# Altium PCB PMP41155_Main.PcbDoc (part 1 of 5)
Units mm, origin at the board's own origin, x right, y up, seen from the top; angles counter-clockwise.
Board outline 74 x 146.5 mm, 8 copper layers (Top Layer, Signal Layer 1, Signal Layer 2, Signal Layer 3, Signal Layer 4, Signal Layer 5, Signal Layer 6, Bottom Layer), stack 1.534 mm thick; 249 components, 190 nets, 902 pads, 747 vias.
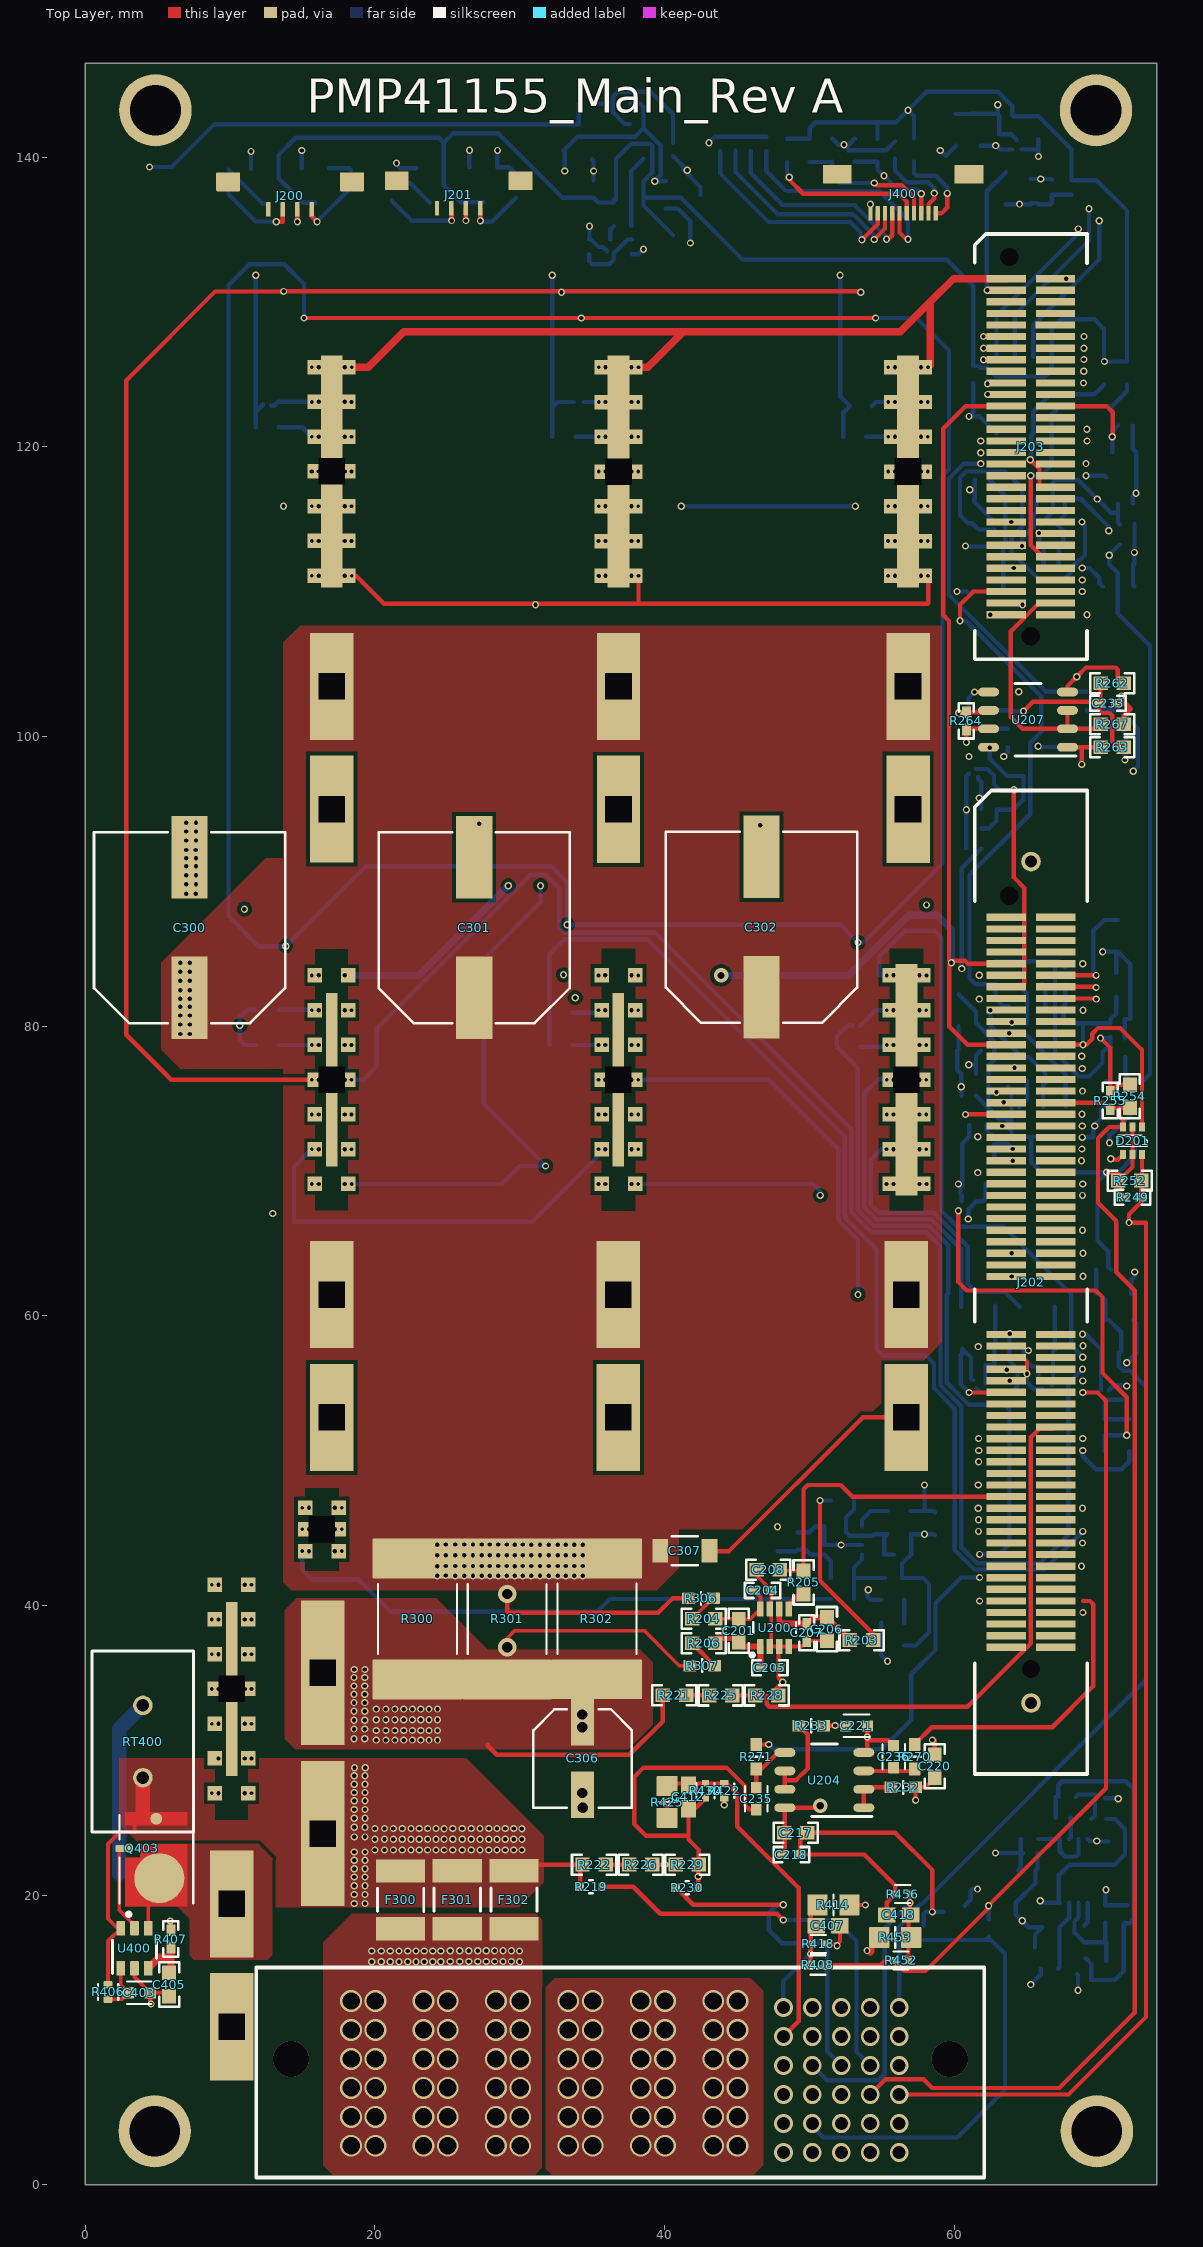
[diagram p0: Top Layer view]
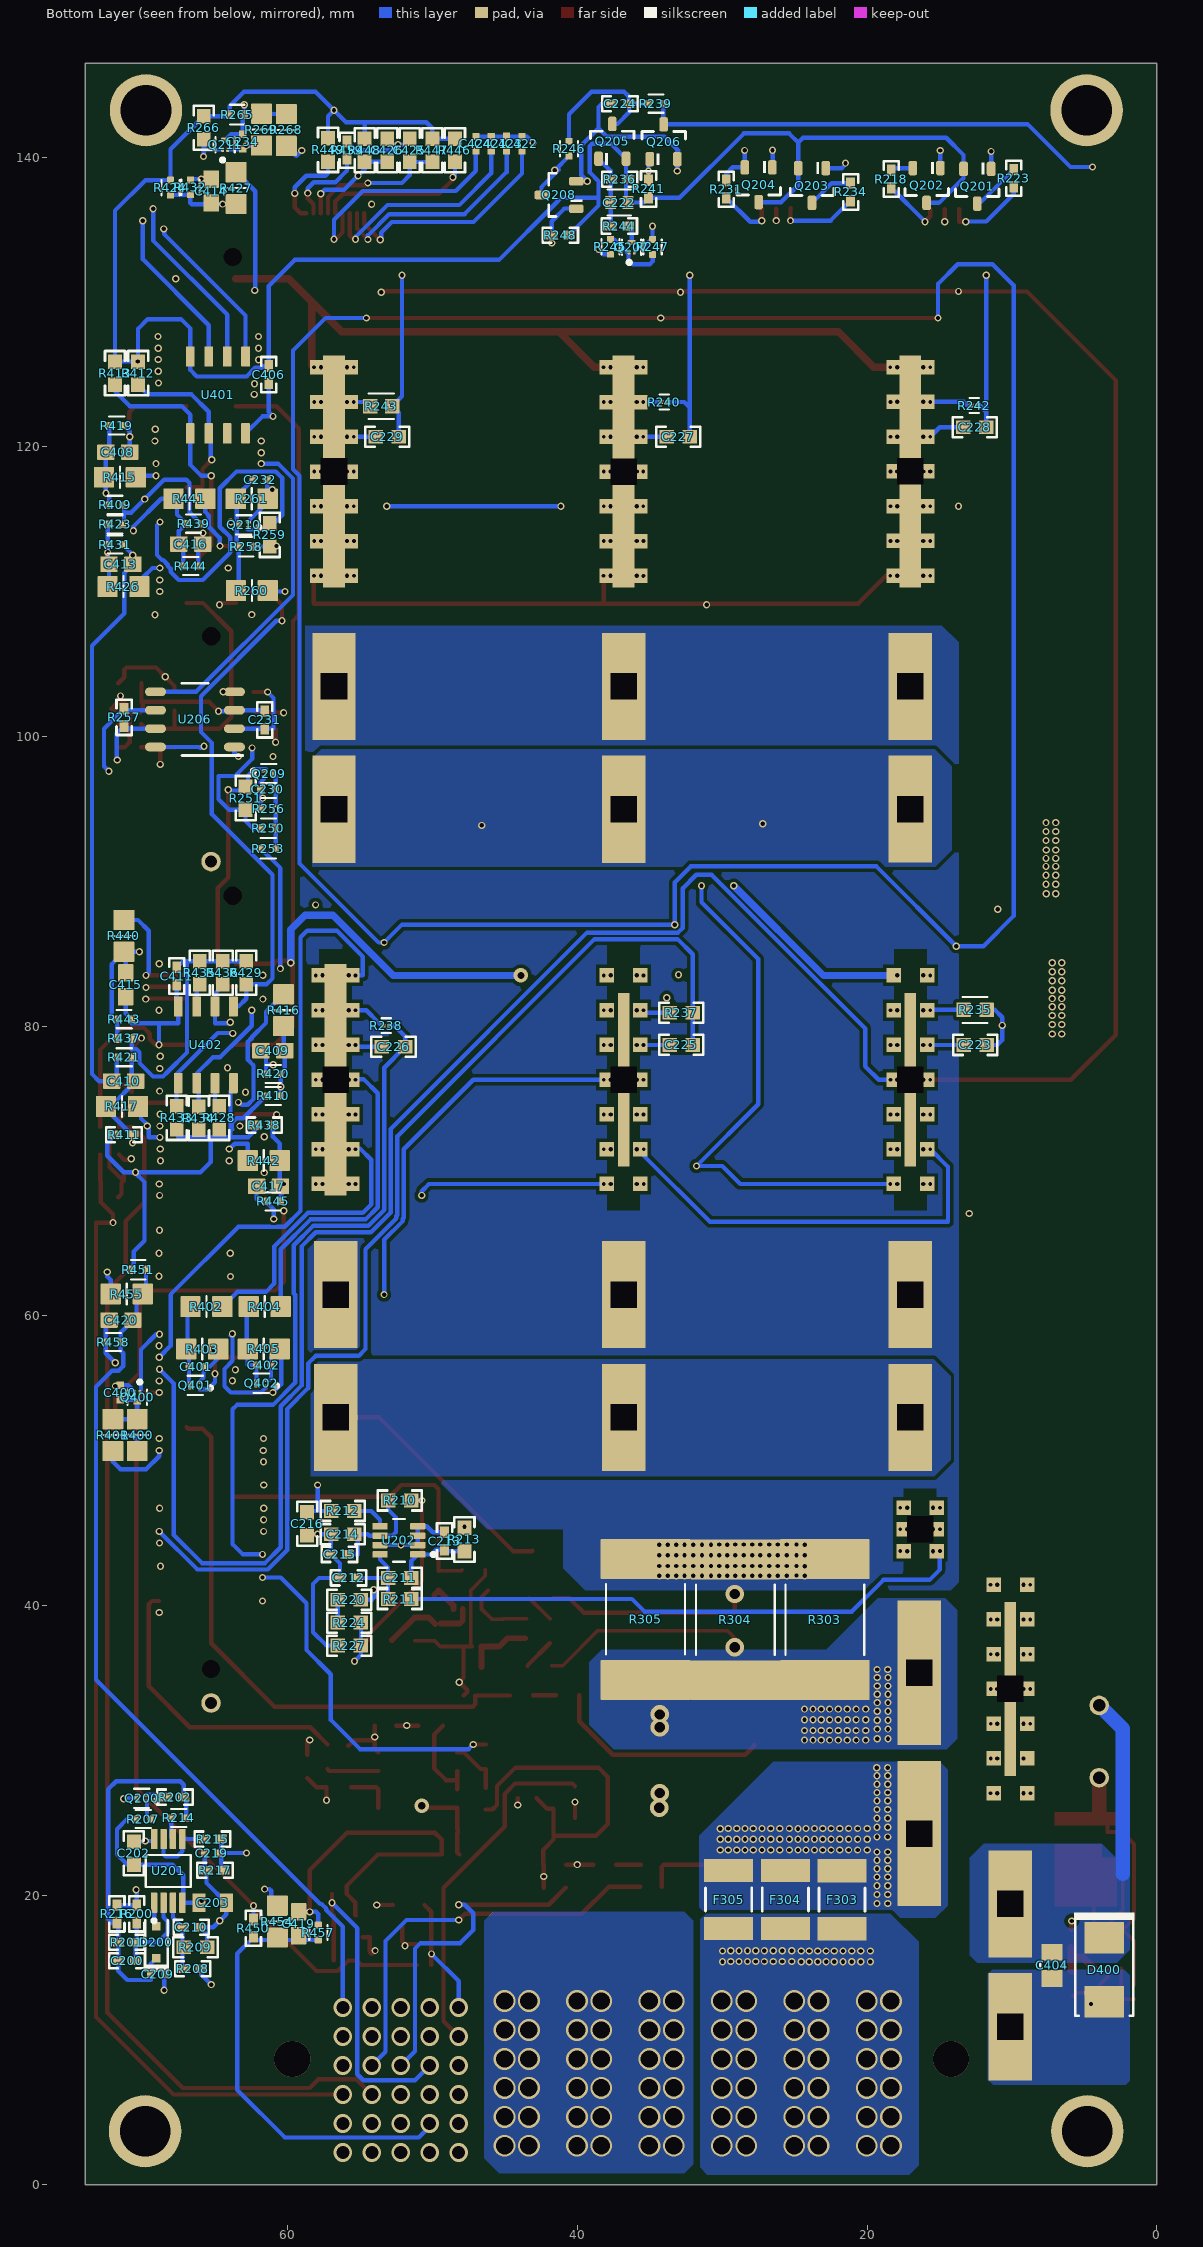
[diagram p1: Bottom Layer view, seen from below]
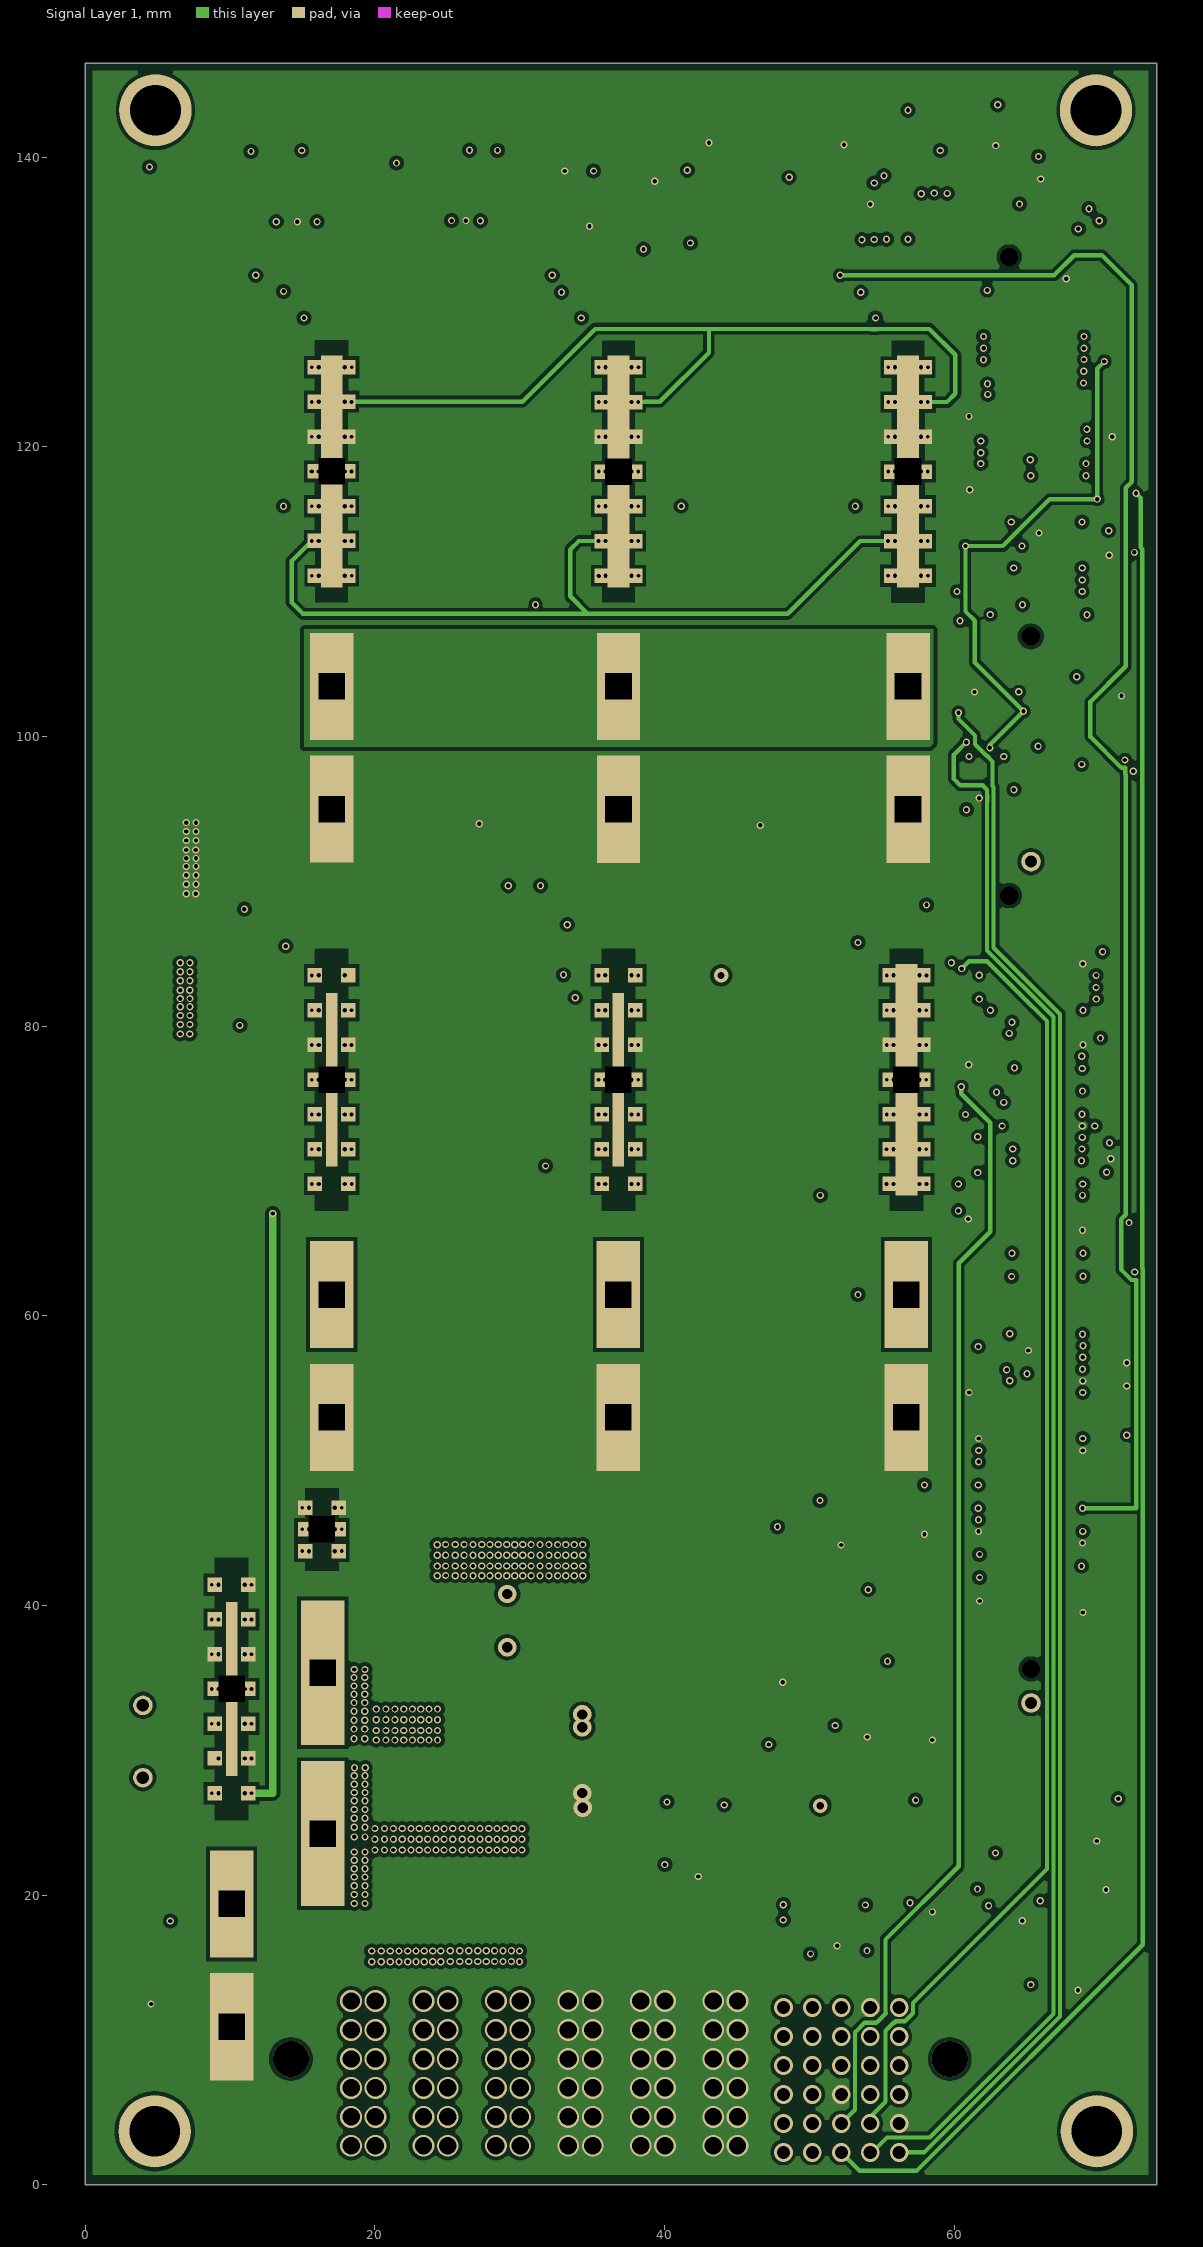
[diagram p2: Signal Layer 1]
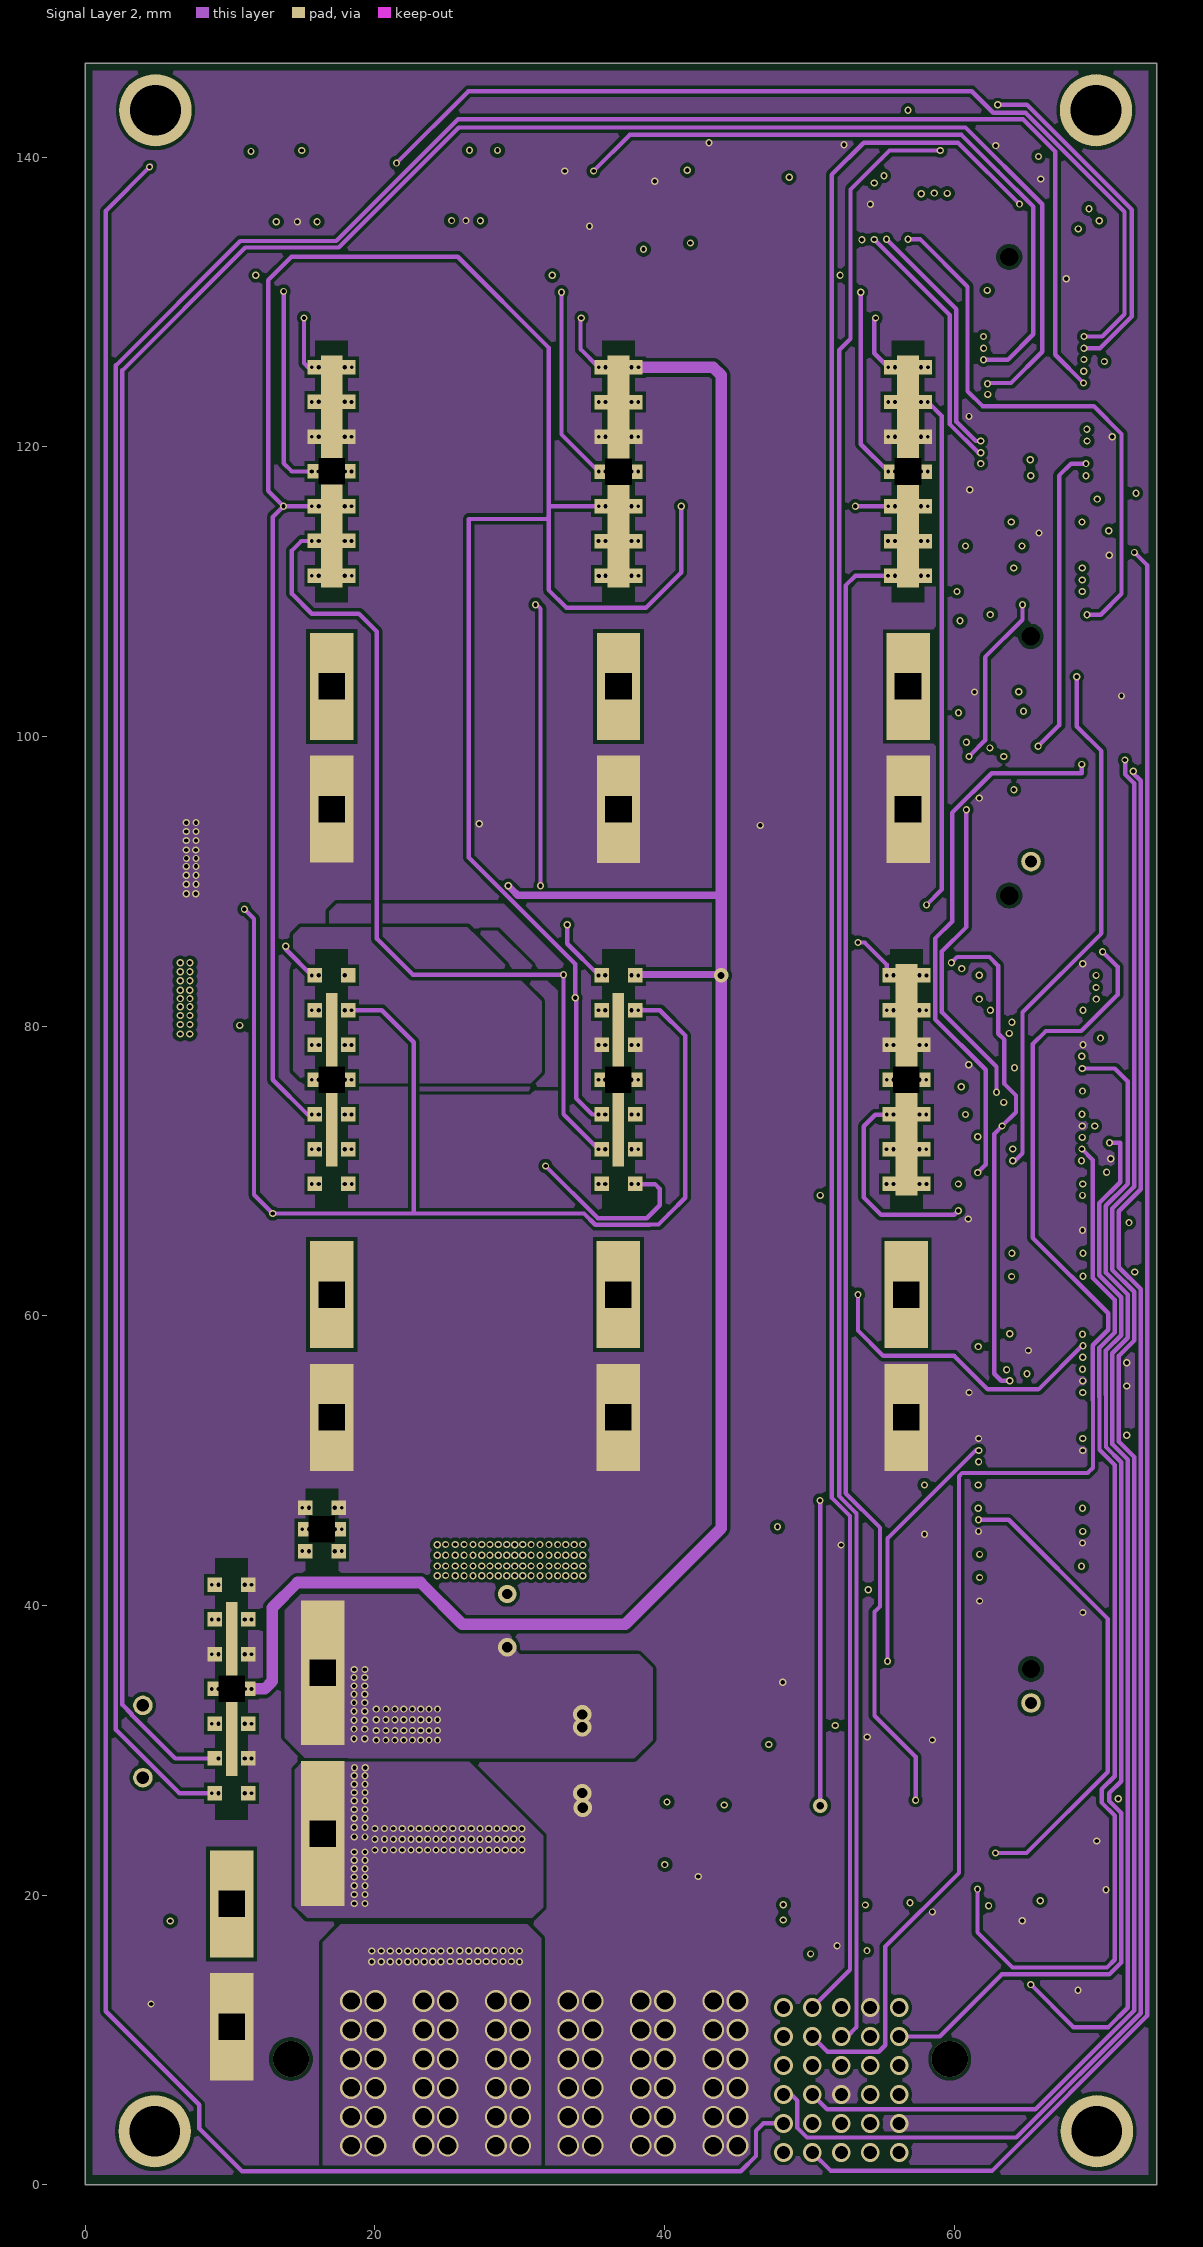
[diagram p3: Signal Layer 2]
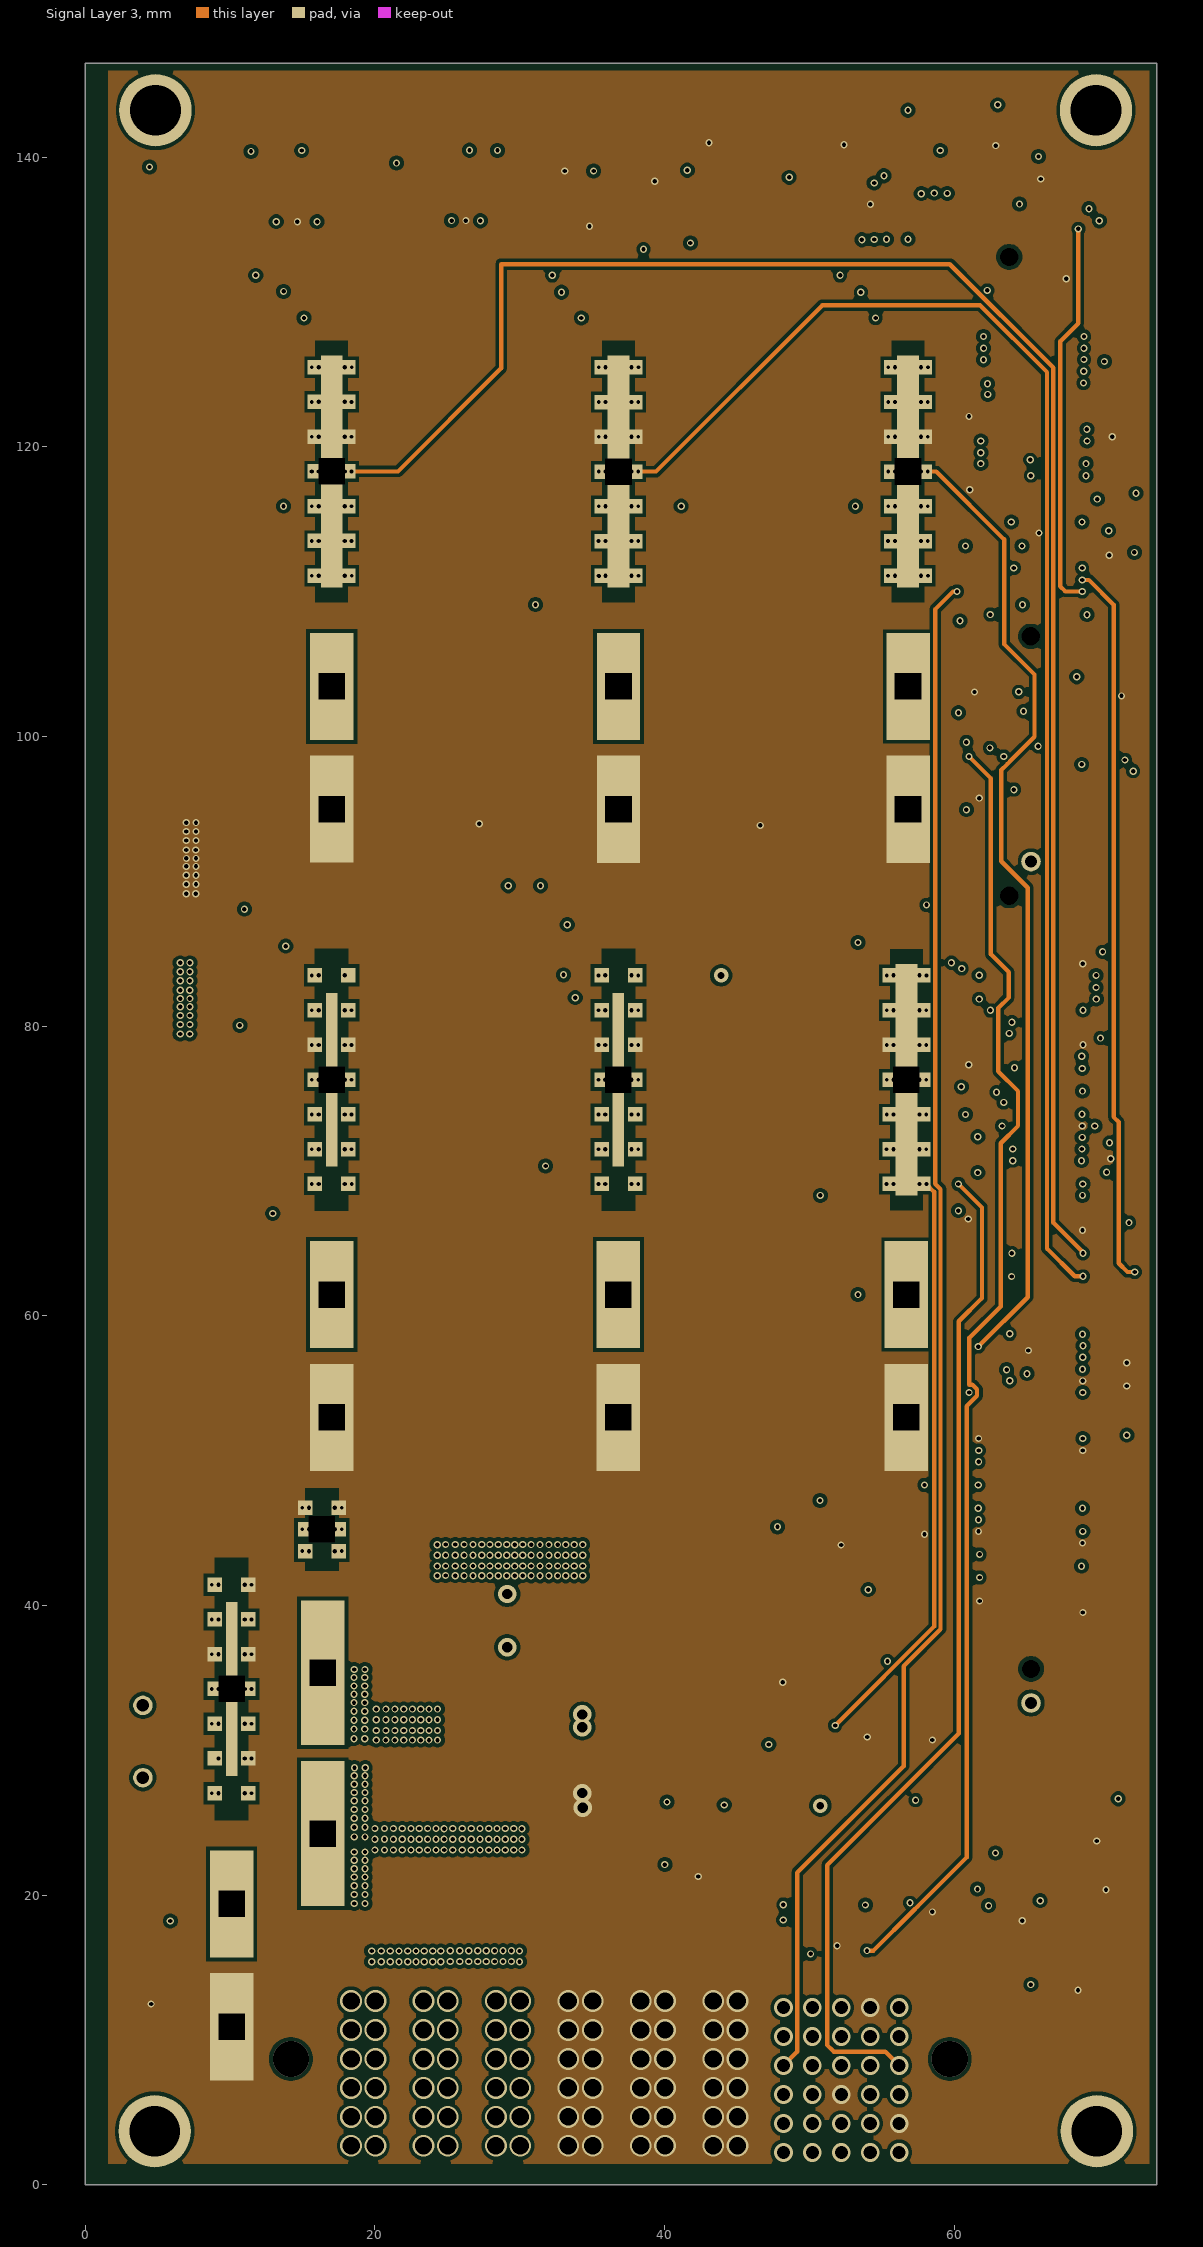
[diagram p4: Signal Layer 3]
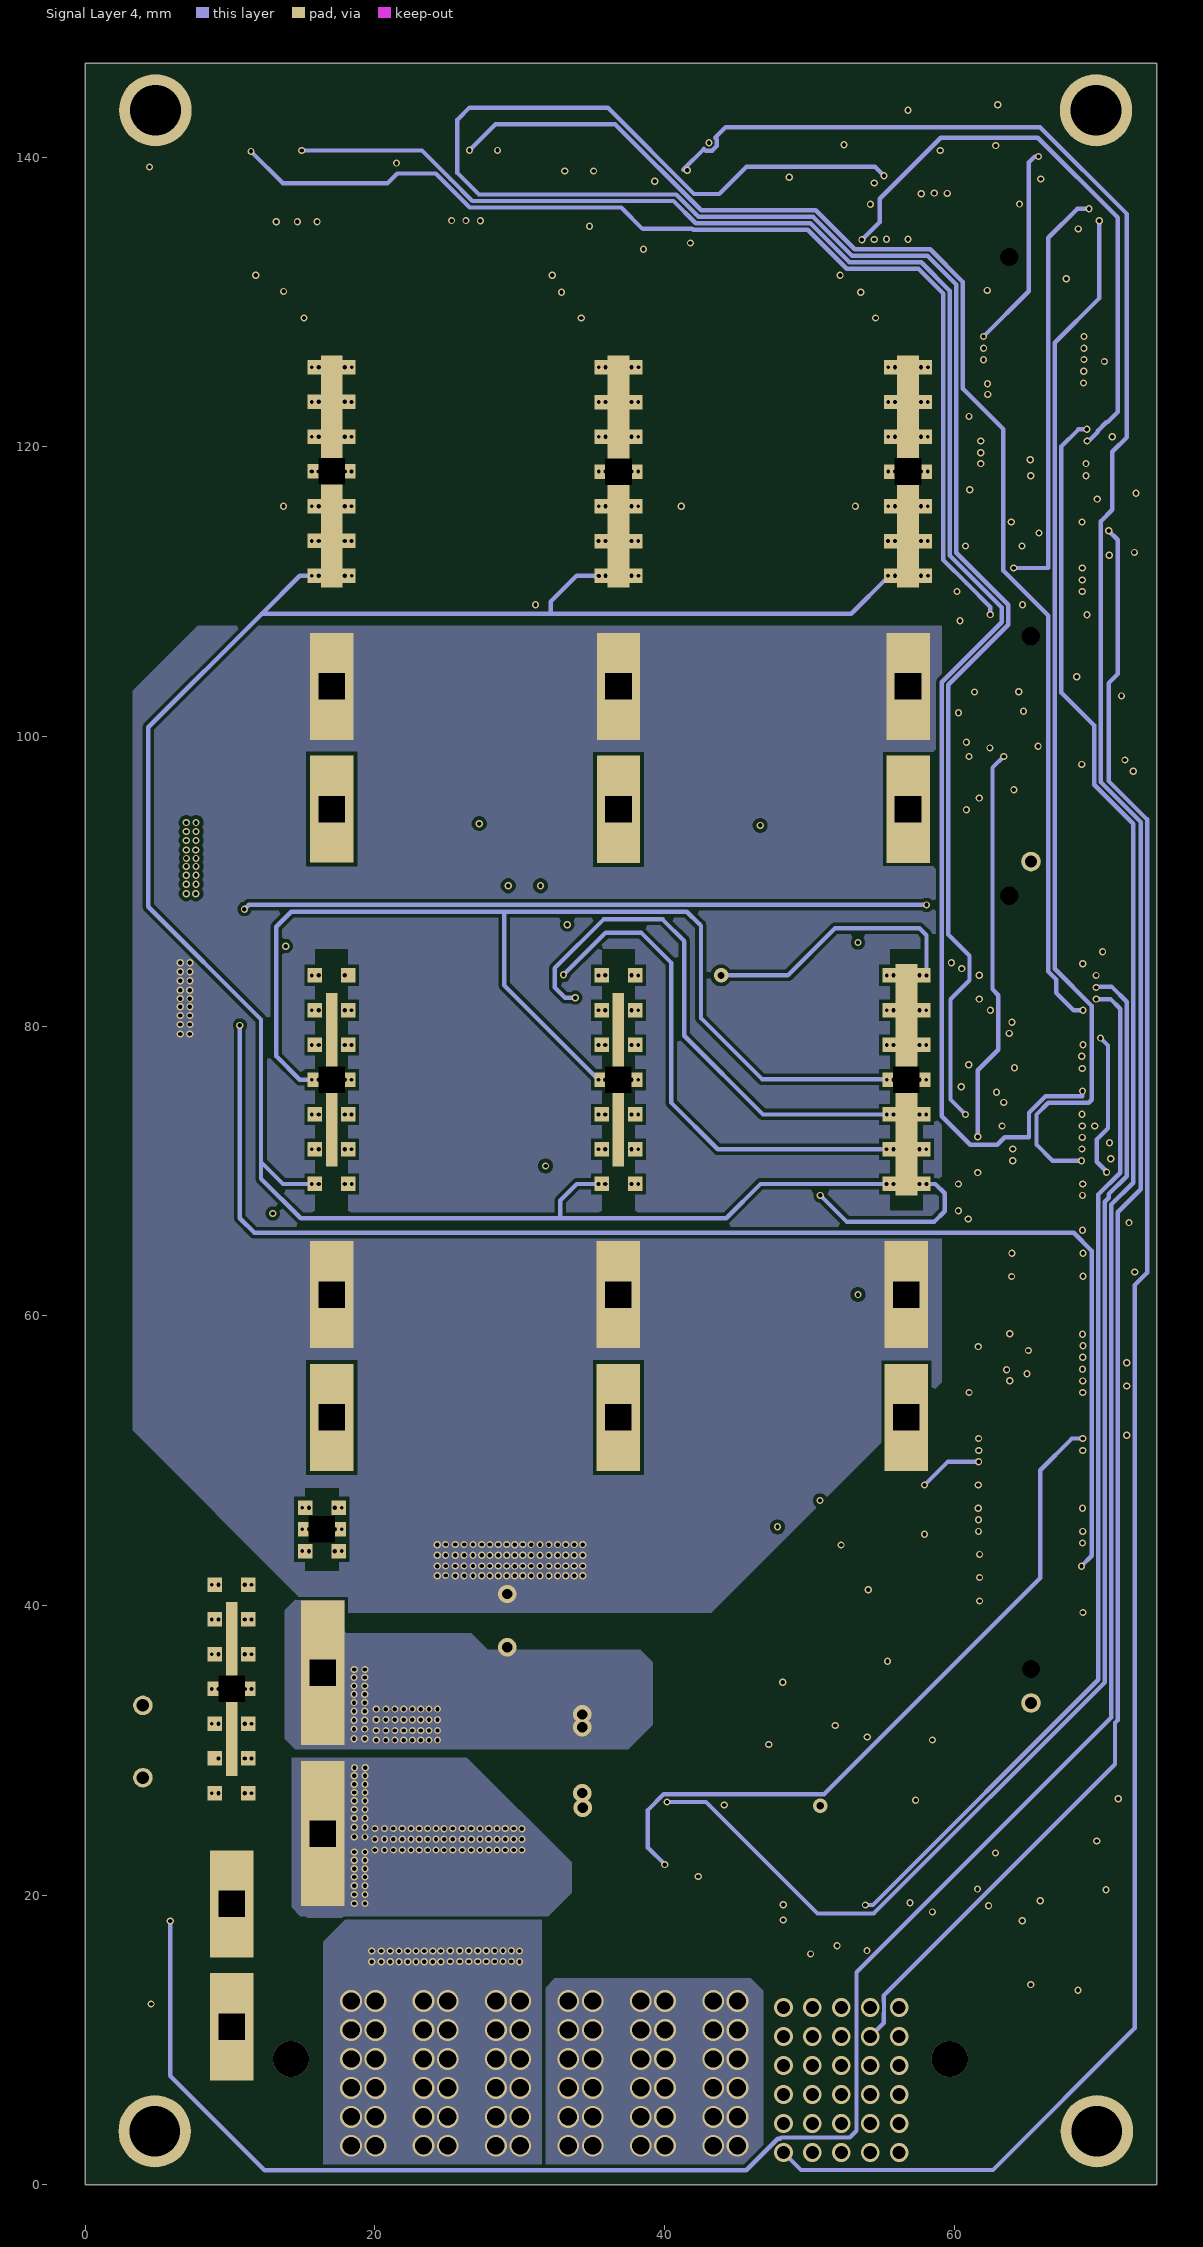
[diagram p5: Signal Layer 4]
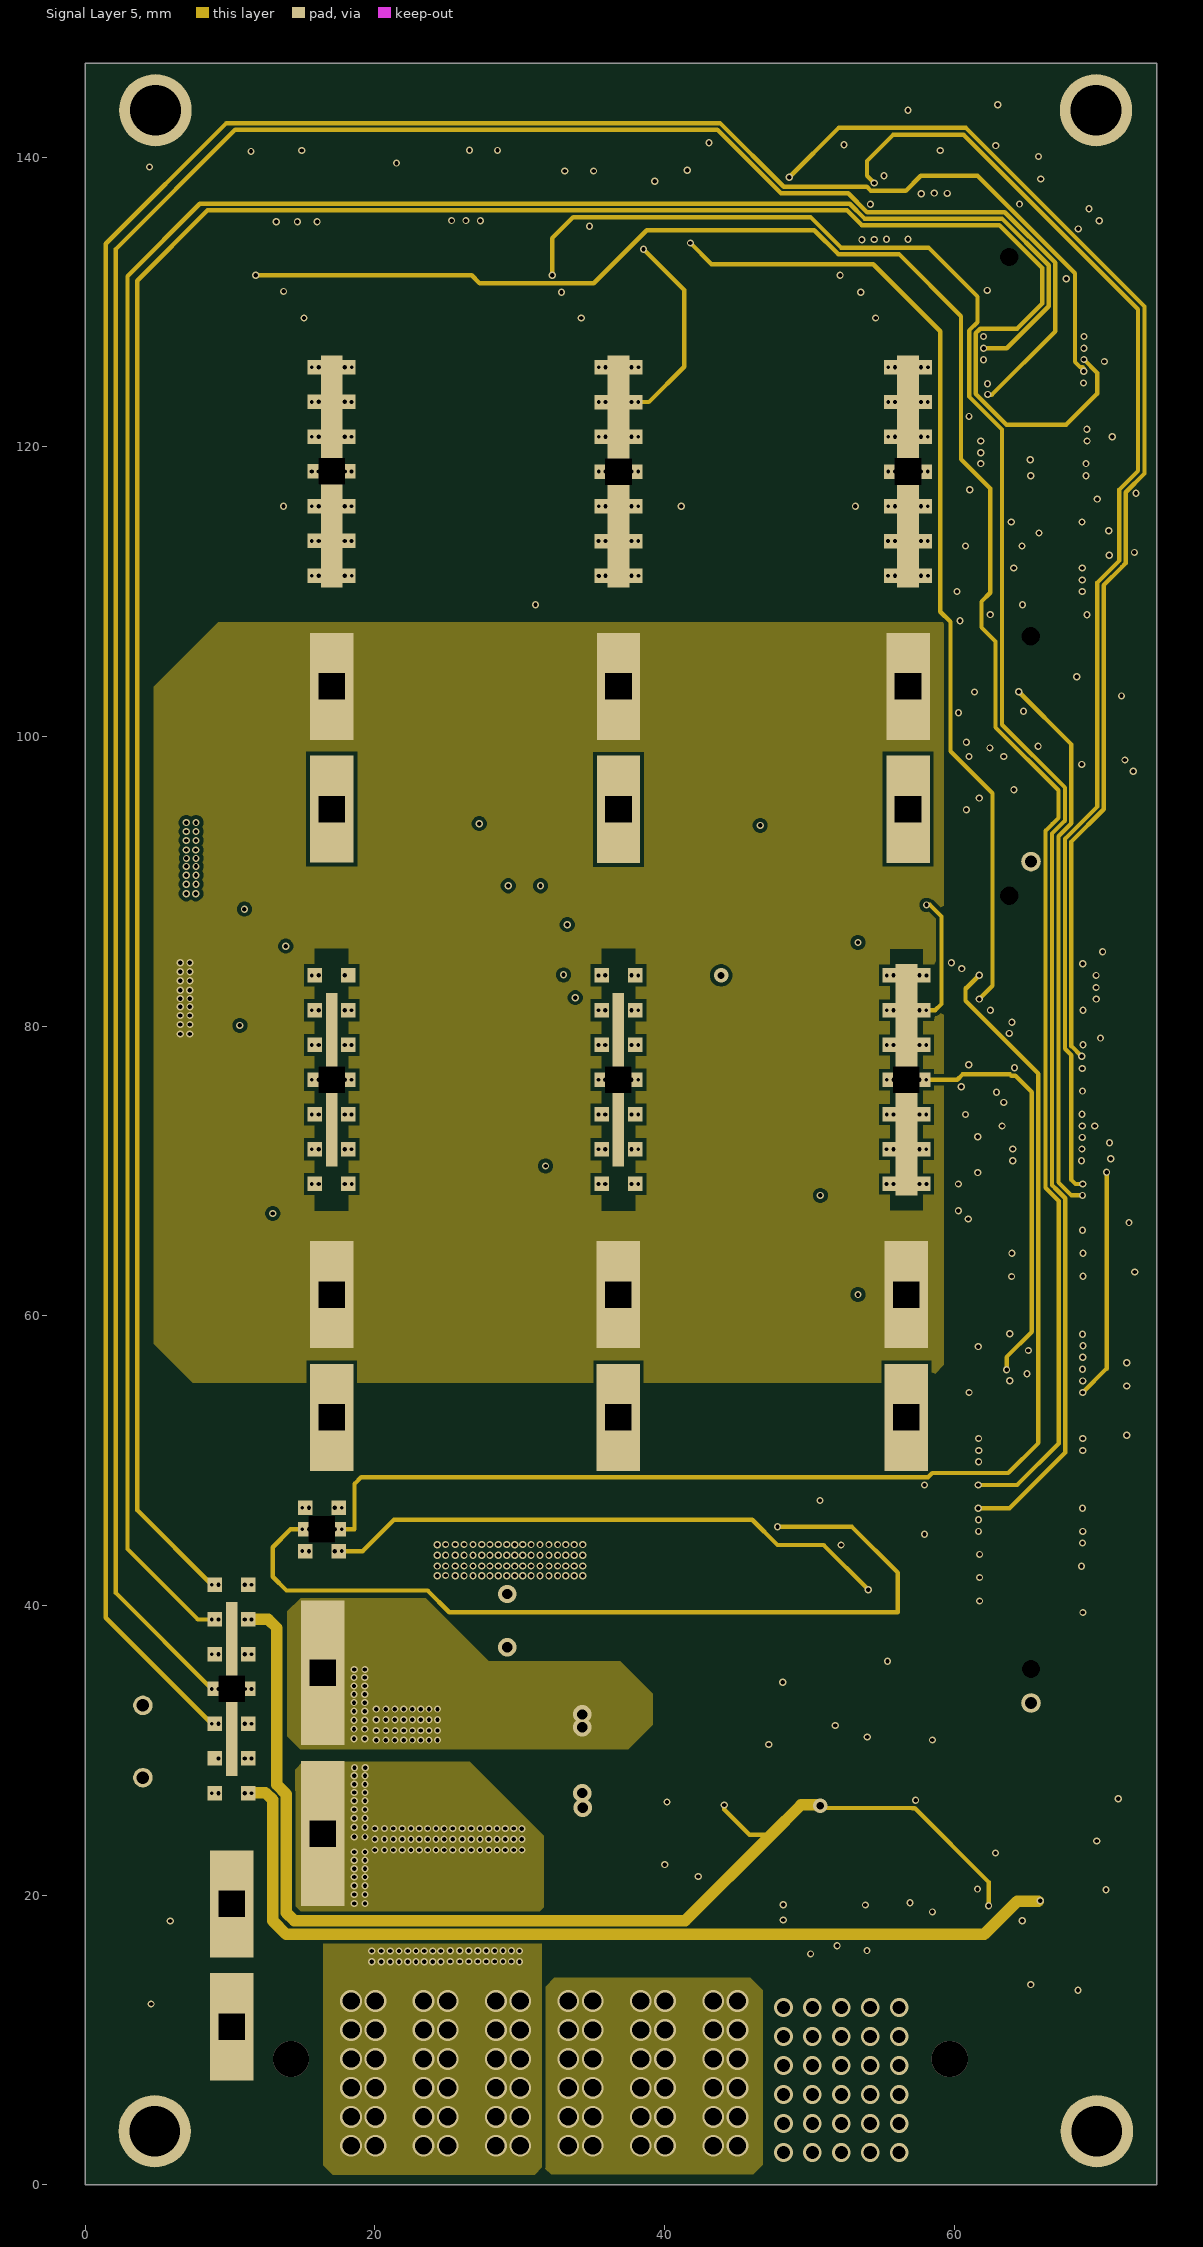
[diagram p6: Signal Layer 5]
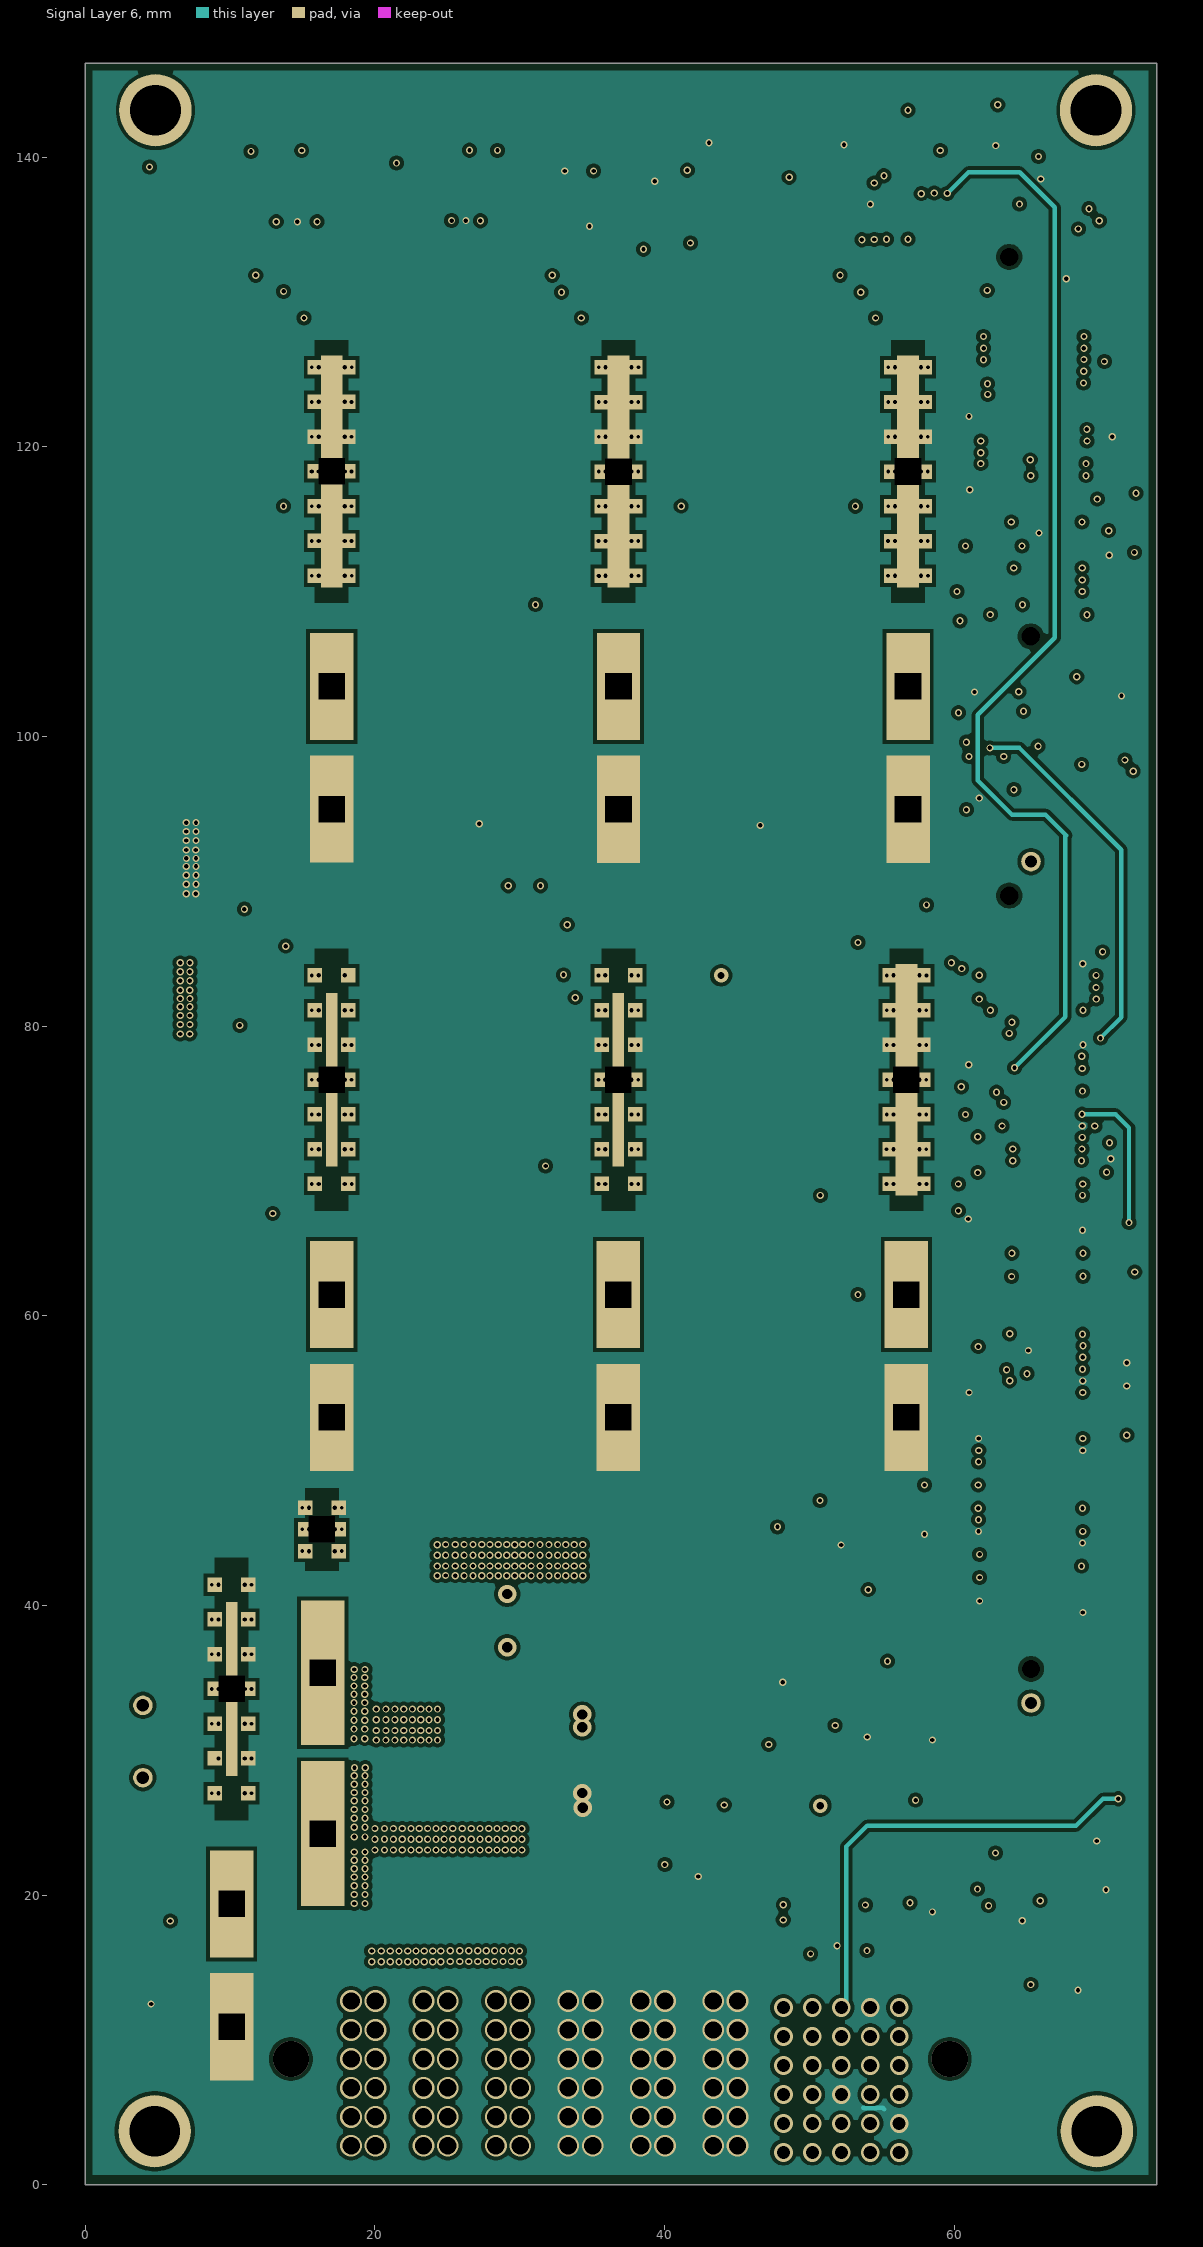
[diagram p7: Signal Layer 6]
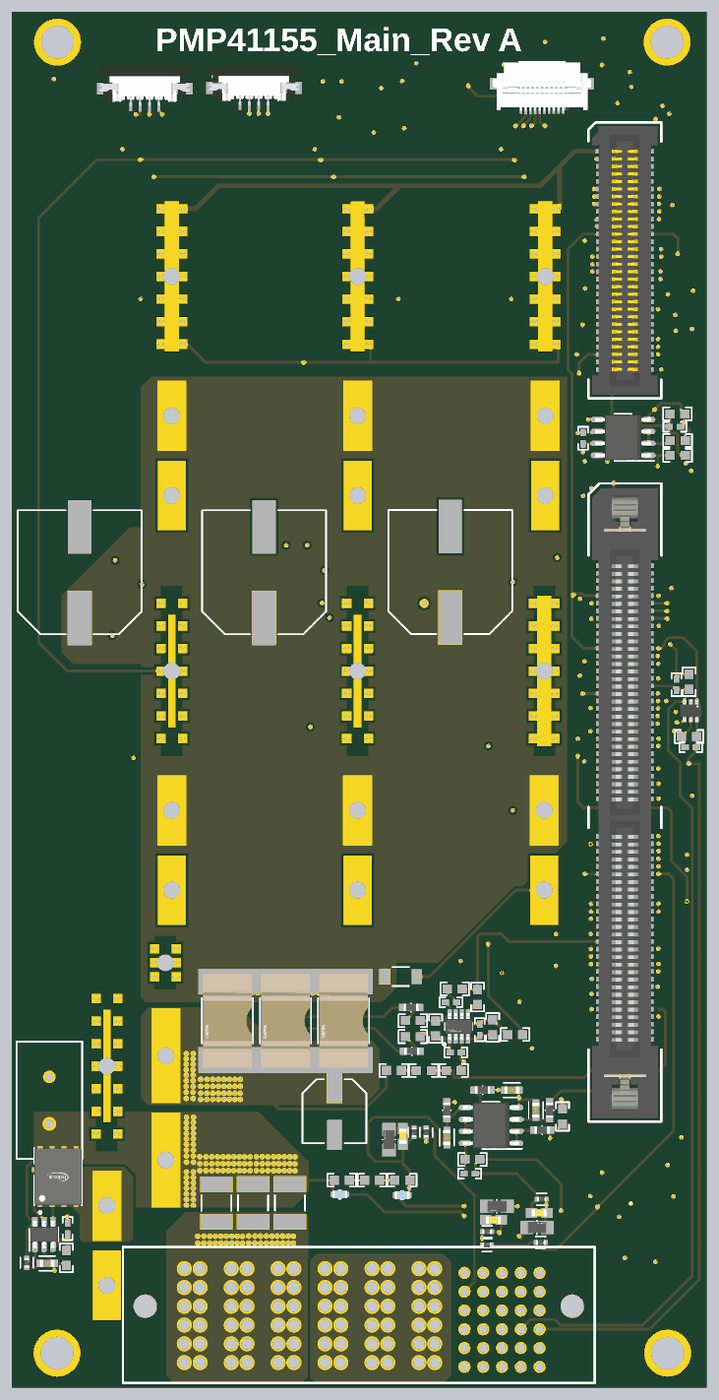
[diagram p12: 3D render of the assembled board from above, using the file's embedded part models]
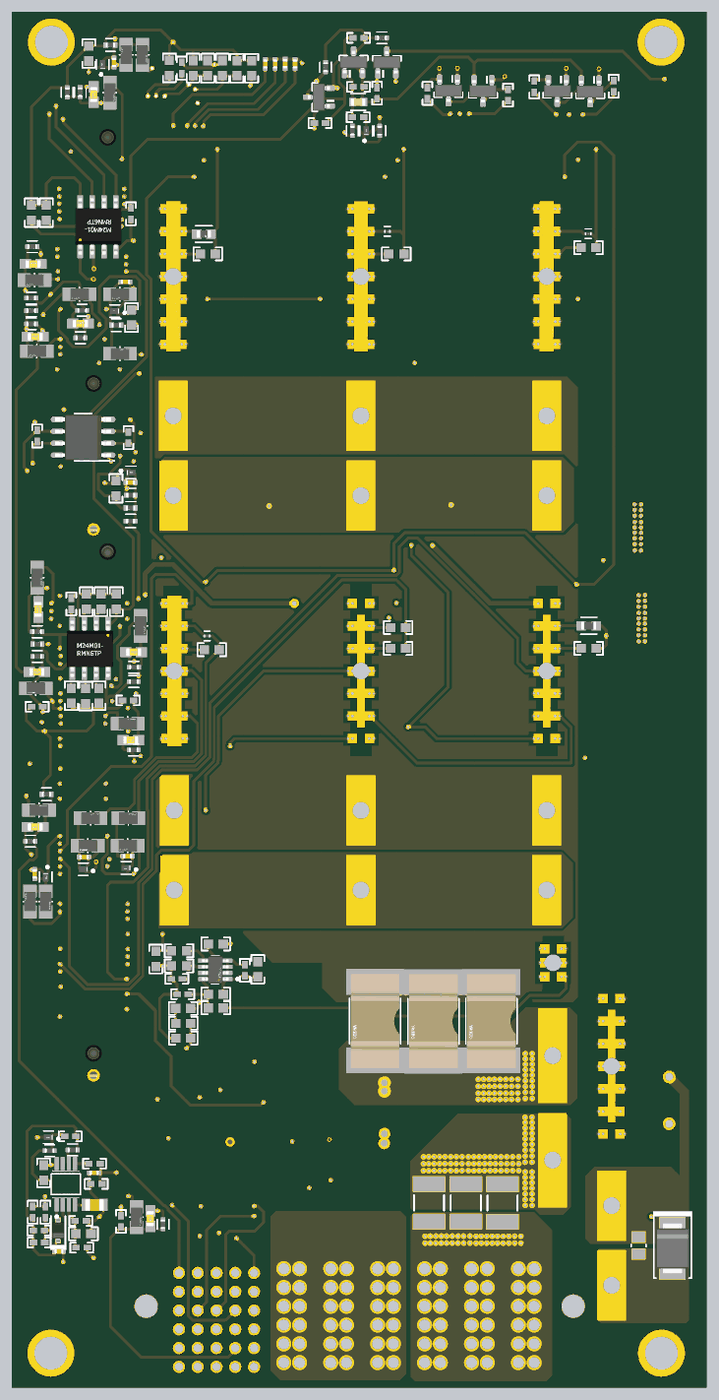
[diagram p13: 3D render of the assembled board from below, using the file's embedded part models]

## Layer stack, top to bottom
Top Solder: solder mask 0.01, Solder Resist, Dk 3.5
Top Layer: signal copper 0.0711
Dielectric1: prepreg 0.127, FR-4, Dk 4.2
Signal Layer 1: signal copper 0.0711
Dielectric 2: core 0.1524, FR-4, Dk 4.2
Signal Layer 2: signal copper 0.0711
Dielectric 3: prepreg 0.127, Dk 4.2
Signal Layer 3: signal copper 0.0711
Dielectric 4: core 0.1524, Dk 4.2
Signal Layer 4: signal copper 0.0711
Dielectric 6: prepreg 0.127, Dk 4.2
Signal Layer 5: signal copper 0.0711
Dielectric 7: core 0.1524, Dk 4.2
Signal Layer 6: signal copper 0.0711
Dielectric 5: prepreg 0.127, Dk 4.2
Bottom Layer: signal copper 0.0711
Bottom Solder: solder mask 0.01, Solder Resist, Dk 3.5

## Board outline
0,0 0,146.5 74,146.5 74,0

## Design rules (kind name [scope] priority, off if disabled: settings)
AcuteAngle [All] p1: minimum=4.50000000000000E+0001 checktracksonly=FALSE
AssemblyTestPointUsage [All] p1: valid=2
BoardOutlineClearance BoardOutlineClearance_MountingHoles [OnCopper and InComponentClass('Mounting Holes')] p1: gap=1.016 ignorepadtopadclearanceinfootprint=FALSE
BoardOutlineClearance BoardOutlineClearance_Poly [OnCopper and IsPoly] p2: gap=0.508 ignorepadtopadclearanceinfootprint=FALSE
BoardOutlineClearance [OnCopper and Not InComponentClass('Logo') and not InComponentClass('FiducialMark') and not InRegion(1000,500,4000,800) and not InPoly] p3: gap=0.254 ignorepadtopadclearanceinfootprint=FALSE
Clearance Clearance_1 [InNetClass('HV') vs Not InNetClass('HV')] p1: gap=0.508 ignorepadtopadclearanceinfootprint=FALSE
Clearance Clearance_Keepouts [((IsTrack Or IsArc) And Not InPoly) And IsFree and IsKeepOut vs ((IsTrack Or IsArc) And Not InPoly) And IsFree and IsKeepOut] p2: gap=0 ignorepadtopadclearanceinfootprint=FALSE
Clearance Clearance_Poly [InPolygon] p3: gap=0.254 ignorepadtopadclearanceinfootprint=FALSE
Clearance Clearance_FiducialMark [IsKeepOut and InComponentClass('FiducialMark') vs IsPad and InComponentClass('FiducialMark')] p4: gap=0 ignorepadtopadclearanceinfootprint=FALSE
Clearance [All] p5: gap=0.147 ignorepadtopadclearanceinfootprint=FALSE
ComponentClearance ComponentClearance_MountingHoles_FiducialMarks [InComponentClass('Mounting Holes') vs InComponentClass('FiducialMark')] p1: gap=1.27 collisioncheckmode=3 verticalgap=0.254 showdistances=FALSE
ComponentClearance ComponentClearance_Shunt [InComponentClass('Header') vs InComponentClass('Shunt')] p2: gap=0 collisioncheckmode=3 verticalgap=0 showdistances=FALSE
ComponentClearance ComponentClearance_Logo [InComponentClass('Logo')] p3: gap=1.27 collisioncheckmode=3 verticalgap=0.254 showdistances=FALSE
ComponentClearance ComponentClearance_ScrewToNut [(HasFootprint('NY PMS 440 0025 PH')) vs (HasFootprint('Keystone_1902C'))] p4: gap=0.127 collisioncheckmode=3 verticalgap=0.254 showdistances=FALSE
ComponentClearance ComponentClearance_MountingHoles [InComponentClass('Mounting Holes')] p5: gap=6.35 collisioncheckmode=3 verticalgap=2540 showdistances=FALSE
ComponentClearance ComponentClearance_SmallPassives [HasFootprint('0201*') or HasFootprint('0402*') or HasFootprint('0508') or HasFootprint('0603*') or HasFootprint('0612') or HasFootprint('0805*') or HasFootprint('0815*') or HasFootprint('0830*') or HasFootprint('1206*') or HasFootprint('1210*') or HasFootprint('1808*') or HasFootprint('1812*') or HasFootprint('1825*') or HasFootprint('2010*') or HasFootprint('2220*') or HasFootprint('2225*') or HasFootprint('2512*') or HasFootprint('2728*') or HasFootprint('3518*') vs HasFootprint('0201*') or HasFootprint('0402*') or HasFootprint('0508') or HasFootprint('0603*') or HasFootprint('0612') or HasFootprint('0805*') or HasFootprint('0815*') or HasFootprint('0830*') or HasFootprint('1206*') or HasFootprint('1210*') or HasFootprint('1808*') or HasFootprint('1812*') or HasFootprint('1825*') or HasFootprint('2010*') or HasFootprint('2220*') or HasFootprint('2225*') or HasFootprint('2512*') or HasFootprint('2728*') or HasFootprint('3518*')] p6: gap=0.254 collisioncheckmode=3 verticalgap=0.254 showdistances=FALSE
ComponentClearance ComponentClearance_THtoSMT [IsThruComponent vs IsSMTComponent] p7: gap=0.508 collisioncheckmode=3 verticalgap=0.762 showdistances=FALSE
ComponentClearance ComponentClearance_THtoTH [IsThruComponent vs IsThruComponent] p8: gap=0.508 collisioncheckmode=3 verticalgap=0.508 showdistances=FALSE
ComponentClearance [All] p9: gap=0.14 collisioncheckmode=3 verticalgap=0.14 showdistances=FALSE
DiffPairsRouting [All] p1: maxlimit=2.54 minlimit=0.254 mostfreqgap=0.254 toplayer_minwidth=0.381 toplayer_maxwidth=0.381 toplayer_prefwidth=0.381 midlayer1_minwidth=0.381 midlayer1_maxwidth=0.381 midlayer1_prefwidth=0.381 midlayer2_minwidth=0.381 midlayer2_maxwidth=0.381 midlayer2_prefwidth=0.381 midlayer3_minwidth=0.381 midlayer3_maxwidth=0.381 midlayer3_prefwidth=0.381 midlayer4_minwidth=0.381 midlayer4_maxwidth=0.381 midlayer4_prefwidth=0.381 midlayer5_minwidth=0.381 midlayer5_maxwidth=0.381 midlayer5_prefwidth=0.381 midlayer6_minwidth=0.381 midlayer6_maxwidth=0.381 midlayer6_prefwidth=0.381 bottomlayer_minwidth=0.381 bottomlayer_maxwidth=0.381 bottomlayer_prefwidth=0.381 maxuncoupledlength=25.4
FabricationTestPointUsage TestPointUsage [All] p1: valid=2 allowmultiple=FALSE
FabricationTestpoint Testpoint [All] p1: side=3 testpointundercomponent=TRUE minsize=1.016 maxsize=2.54 preferedsize=1.524 minholesize=0 maxholesize=1.016 preferedholesize=0.813 testpointgrid=0.025 allowsidetop=TRUE allowsidebottom=TRUE usegrid=TRUE gridtolerance=0
FanoutControl Fanout_LCC [IsLCC] p1: bgadir=Out bgaviamode=Centered fanoutstyle=Auto fanoutdirection=Alternating viagrid=0.025 // Fanout_LCC (Default Rule)
FanoutControl Fanout_BGA [IsBGA] p2: bgadir=Out bgaviamode=Centered fanoutstyle=Auto fanoutdirection=Alternating viagrid=0.025 // Fanout_BGA (Default Rule)
FanoutControl Fanout_Default [All] p4: bgadir=Out bgaviamode=Centered fanoutstyle=Auto fanoutdirection=Alternating viagrid=0.025 // Fanout_Default (Default Rule)
FanoutControl Fanout_Small [(CompPinCount < 5)] p5: bgadir=Out bgaviamode=Centered fanoutstyle=Auto fanoutdirection=OutThenIn viagrid=0.025 // Fanout_Small (Default Rule)
HoleSize [All] p1: absolutevalues=TRUE maxlimit=6.604 minlimit=0.2 maxpercent=80.000 minpercent=20.000
MinimumAnnularRing MinimumAnnularRing_ThermalPadVias [IsVia and InAnyComponent] p1: minimumring=0.15
MinimumAnnularRing [All] p2: minimumring=0.127
MinimumSolderMaskSliver MinimumSolderMaskSliver_Logo [InComponentClass('Logo') vs InComponentClass('Logo')] p1: minsoldermaskwidth=0.018
MinimumSolderMaskSliver [All] p2: minsoldermaskwidth=0.076
PlaneClearance [All] p1: clearance=0
PlaneConnect [All] p1: planeconnectstyle=Direct reliefexpansion=0.254 reliefentries=4 reliefconductorwidth=0.254 reliefairgap=0
PolygonConnect PolygonConnect_32 [All vs IsNamedPolygon('5V') Or  IsNamedPolygon('CS-_total_charge_current_battery') Or  IsNamedPolygon('5V') Or  IsNamedPolygon('CS-_total_charge_current_battery') Or  IsNamedPolygon('48Vout2') Or  IsNamedPolygon('48VOUT1') Or  IsNamedPolygon('SGND') Or  IsNamedPolygon('48Vout2') Or  IsNamedPolygon('CS-_total_discharge_current_bus') Or  IsNamedPolygon('5V') Or  IsNamedPolygon('48Vout2') Or  IsNamedPolygon('5V') Or  IsNamedPolygon('5V') Or  IsNamedPolygon('VBAT-') Or  IsNamedPolygon('5V') Or  IsNamedPolygon('48Vout2') Or  IsNamedPolygon('VBAT-') Or  IsNamedPolygon('48Vout2') Or  IsNamedPolygon('5V') Or  IsNamedPolygon('5V') Or  IsNamedPolygon('48Vout2') Or  IsNamedPolygon('5V') Or  IsNamedPolygon('CS-_total_charge_current_battery') Or  IsNamedPolygon('SGND') Or  IsNamedPolygon('SGND') Or  IsNamedPolygon('SGND') Or  IsNamedPolygon('CS-_total_discharge_current_bus') Or  IsNamedPolygon('SGND') Or  IsNamedPolygon('SGND') Or  IsNamedPolygon('CS-_total_charge_current_battery') Or  IsNamedPolygon('SGND') Or  IsNamedPolygon('48Vout1') Or  IsNamedPolygon('SGND') Or  IsNamedPolygon('CS-_total_charge_current_battery') Or  IsNamedPolygon('SGND') Or  IsNamedPolygon('VBAT-') Or  IsNamedPolygon('CS-_total_discharge_current_bus') Or  IsNamedPolygon('VBAT-') Or  IsNamedPolygon('VBAT-') Or  IsNamedPolygon('VBAT-') Or  IsNamedPolygon('CS-_total_discharge_current_bus') Or  IsNamedPolygon('SGND') Or  IsNamedPolygon('48Vout2') Or  IsNamedPolygon('VBAT-') Or  IsNamedPolygon('48Vout2') Or  IsNamedPolygon('VBAT-') Or  IsNamedPolygon('CS-') Or  IsNamedPolygon('SGND') Or  IsNamedPolygon('VBAT-') Or  IsNamedPolygon('SGND') Or  IsNamedPolygon('VBAT-') Or  IsNamedPolygon('48Vout1') Or  IsNamedPolygon('VBAT-') Or  IsNamedPolygon('CS-') Or  IsNamedPolygon('SGND') Or  IsNamedPolygon('48Vout1') Or  IsNamedPolygon('SGND') Or  IsNamedPolygon('VBAT-') Or  IsNamedPolygon('SGND') Or  IsNamedPolygon('CS-_total_charge_current_battery') Or  IsNamedPolygon('CS-_total_charge_current_battery') Or  IsNamedPolygon('VBAT-') Or  IsNamedPolygon('CS-_total_discharge_current_bus') Or  IsNamedPolygon('SGND') Or  IsNamedPolygon('CS-_total_charge_current_battery') Or  IsNamedPolygon('CS+_total_charge_current_battery') Or  IsNamedPolygon('48Vout1') Or  IsNamedPolygon('VBAT-') Or  IsNamedPolygon('SGND') Or  IsNamedPolygon('CS-_total_discharge_current_bus') Or  IsNamedPolygon('CS-_total_discharge_current_bus') Or  IsNamedPolygon('48Vout1') Or  IsNamedPolygon('SGND') Or  IsNamedPolygon('SGND') Or  IsNamedPolygon('CS-_total_charge_current_battery') Or  IsNamedPolygon('SGND') Or  IsNamedPolygon('VBAT-') Or  IsNamedPolygon('SGND') Or  IsNamedPolygon('SGND') Or  IsNamedPolygon('SGND') Or  IsNamedPolygon('VBAT-') Or  IsNamedPolygon('48Vout2') Or  IsNamedPolygon('VBAT-') Or  IsNamedPolygon('CS-_total_charge_current_battery') Or  IsNamedPolygon('CS-_total_charge_current_battery') Or  IsNamedPolygon('48Vout1') Or  IsNamedPolygon('SGND') Or  IsNamedPolygon('SGND') Or  IsNamedPolygon('CS+_total_charge_current_battery') Or  IsNamedPolygon('CS-_total_discharge_current_bus') Or  IsNamedPolygon('SGND') Or  IsNamedPolygon('48Vout1') Or  IsNamedPolygon('CS-_total_discharge_current_bus') Or  IsNamedPolygon('48V2') Or  IsNamedPolygon('CS-')] p1: connectstyle=Direct reliefconductorwidth=0.254 reliefentries=4 polygonreliefangle="90 Angle" airgapwidth=0.254
PolygonConnect PolygonConnect_31 [All vs IsNamedPolygon('CS-_total_charge_current_battery') Or  IsNamedPolygon('5V') Or  IsNamedPolygon('5V') Or  IsNamedPolygon('48Vout2') Or  IsNamedPolygon('CS-_total_discharge_current_bus') Or  IsNamedPolygon('5V') Or  IsNamedPolygon('VBAT-') Or  IsNamedPolygon('48Vout2') Or  IsNamedPolygon('5V') Or  IsNamedPolygon('5V') Or  IsNamedPolygon('CS-_total_charge_current_battery') Or  IsNamedPolygon('48Vout2') Or  IsNamedPolygon('VBAT-') Or  IsNamedPolygon('5V') Or  IsNamedPolygon('48Vout2') Or  IsNamedPolygon('5V') Or  IsNamedPolygon('48Vout2') Or  IsNamedPolygon('48Vout2') Or  IsNamedPolygon('VBAT-') Or  IsNamedPolygon('VBAT-') Or  IsNamedPolygon('VBAT-') Or  IsNamedPolygon('48Vout1') Or  IsNamedPolygon('VBAT-') Or  IsNamedPolygon('48Vout1') Or  IsNamedPolygon('48Vout1') Or  IsNamedPolygon('VBAT-') Or  IsNamedPolygon('CS-_total_charge_current_battery') Or  IsNamedPolygon('CS-_total_discharge_current_bus') Or  IsNamedPolygon('CS-') Or  IsNamedPolygon('48Vout2') Or  IsNamedPolygon('CS-_total_charge_current_battery') Or  IsNamedPolygon('VBAT-') Or  IsNamedPolygon('CS+_total_charge_current_battery') Or  IsNamedPolygon('VBAT-') Or  IsNamedPolygon('CS-_total_charge_current_battery') Or  IsNamedPolygon('VBAT-') Or  IsNamedPolygon('48Vout2') Or  IsNamedPolygon('VBAT-') Or  IsNamedPolygon('VBAT-') Or  IsNamedPolygon('CS-') Or  IsNamedPolygon('CS-_total_discharge_current_bus') Or  IsNamedPolygon('CS-_total_discharge_current_bus') Or  IsNamedPolygon('CS-_total_charge_current_battery') Or  IsNamedPolygon('VBAT-') Or  IsNamedPolygon('VBAT-') Or  IsNamedPolygon('VBAT-') Or  IsNamedPolygon('VBAT-') Or  IsNamedPolygon('VBAT-') Or  IsNamedPolygon('VBAT-') Or  IsNamedPolygon('VBAT-') Or  IsNamedPolygon('CS-_total_charge_current_battery') Or  IsNamedPolygon('VBAT-') Or  IsNamedPolygon('VBAT-') Or  IsNamedPolygon('VBAT-') Or  IsNamedPolygon('VBAT-') Or  IsNamedPolygon('CS-_total_discharge_current_bus') Or  IsNamedPolygon('48V2') Or  IsNamedPolygon('5V') Or  IsNamedPolygon('CS-_total_discharge_current_bus') Or  IsNamedPolygon('48Vout1') Or  IsNamedPolygon('48Vout1') Or  IsNamedPolygon('VBAT-') Or  IsNamedPolygon('VBAT-') Or  IsNamedPolygon('CS-_total_charge_current_battery') Or  IsNamedPolygon('VBAT-') Or  IsNamedPolygon('VBAT-') Or  IsNamedPolygon('CS-_total_discharge_current_bus') Or  IsNamedPolygon('VBAT-') Or  IsNamedPolygon('VBAT-') Or  IsNamedPolygon('CS-_total_discharge_current_bus') Or  IsNamedPolygon('CS-') Or  IsNamedPolygon('48VOUT1') Or  IsNamedPolygon('VBAT-') Or  IsNamedPolygon('48Vout1') Or  IsNamedPolygon('5V') Or  IsNamedPolygon('48Vout1') Or  IsNamedPolygon('VBAT-') Or  IsNamedPolygon('VBAT-') Or  IsNamedPolygon('CS-_total_charge_current_battery') Or  IsNamedPolygon('VBAT-') Or  IsNamedPolygon('VBAT-') Or  IsNamedPolygon('VBAT-') Or  IsNamedPolygon('VBAT-') Or  IsNamedPolygon('VBAT-') Or  IsNamedPolygon('CS+_total_charge_current_battery') Or  IsNamedPolygon('VBAT-')] p2: connectstyle=Direct reliefconductorwidth=0.254 reliefentries=4 polygonreliefangle="90 Angle" airgapwidth=0.254
PolygonConnect PolygonConnect_30 [All vs IsNamedPolygon('48Vout2') Or  IsNamedPolygon('VBAT-') Or  IsNamedPolygon('VBAT-') Or  IsNamedPolygon('CS-_total_charge_current_battery') Or  IsNamedPolygon('48Vout1') Or  IsNamedPolygon('5V') Or  IsNamedPolygon('VBAT-') Or  IsNamedPolygon('48Vout2') Or  IsNamedPolygon('VBAT-') Or  IsNamedPolygon('CS-_total_discharge_current_bus') Or  IsNamedPolygon('CS+_total_charge_current_battery') Or  IsNamedPolygon('VBAT-') Or  IsNamedPolygon('CS-_total_charge_current_battery') Or  IsNamedPolygon('48VOUT1') Or  IsNamedPolygon('VBAT-') Or  IsNamedPolygon('VBAT-') Or  IsNamedPolygon('CS-_total_discharge_current_bus') Or  IsNamedPolygon('VBAT-') Or  IsNamedPolygon('5V') Or  IsNamedPolygon('48Vout2') Or  IsNamedPolygon('CS-_total_charge_current_battery') Or  IsNamedPolygon('VBAT-') Or  IsNamedPolygon('5V') Or  IsNamedPolygon('VBAT-') Or  IsNamedPolygon('5V') Or  IsNamedPolygon('VBAT-') Or  IsNamedPolygon('CS-_total_discharge_current_bus') Or  IsNamedPolygon('VBAT-') Or  IsNamedPolygon('48Vout1') Or  IsNamedPolygon('CS-_total_discharge_current_bus') Or  IsNamedPolygon('VBAT-') Or  IsNamedPolygon('5V') Or  IsNamedPolygon('48Vout2') Or  IsNamedPolygon('CS-') Or  IsNamedPolygon('VBAT-') Or  IsNamedPolygon('CS+_total_charge_current_battery') Or  IsNamedPolygon('VBAT-') Or  IsNamedPolygon('VBAT-') Or  IsNamedPolygon('CS-_total_charge_current_battery') Or  IsNamedPolygon('48Vout2') Or  IsNamedPolygon('VBAT-') Or  IsNamedPolygon('CS-_total_charge_current_battery') Or  IsNamedPolygon('48Vout1') Or  IsNamedPolygon('CS-_total_charge_current_battery') Or  IsNamedPolygon('48Vout2') Or  IsNamedPolygon('VBAT-') Or  IsNamedPolygon('VBAT-') Or  IsNamedPolygon('VBAT-') Or  IsNamedPolygon('VBAT-') Or  IsNamedPolygon('CS-') Or  IsNamedPolygon('48Vout1') Or  IsNamedPolygon('CS-') Or  IsNamedPolygon('CS-_total_charge_current_battery') Or  IsNamedPolygon('VBAT-') Or  IsNamedPolygon('VBAT-') Or  IsNamedPolygon('48Vout1') Or  IsNamedPolygon('CS-_total_discharge_current_bus') Or  IsNamedPolygon('VBAT-') Or  IsNamedPolygon('VBAT-') Or  IsNamedPolygon('VBAT-') Or  IsNamedPolygon('CS-_total_discharge_current_bus') Or  IsNamedPolygon('5V') Or  IsNamedPolygon('48Vout2') Or  IsNamedPolygon('VBAT-') Or  IsNamedPolygon('VBAT-') Or  IsNamedPolygon('VBAT-') Or  IsNamedPolygon('48Vout1') Or  IsNamedPolygon('VBAT-') Or  IsNamedPolygon('5V') Or  IsNamedPolygon('VBAT-') Or  IsNamedPolygon('VBAT-') Or  IsNamedPolygon('VBAT-') Or  IsNamedPolygon('5V') Or  IsNamedPolygon('48V2') Or  IsNamedPolygon('CS-_total_discharge_current_bus') Or  IsNamedPolygon('VBAT-') Or  IsNamedPolygon('VBAT-') Or  IsNamedPolygon('CS-_total_charge_current_battery') Or  IsNamedPolygon('48Vout1') Or  IsNamedPolygon('VBAT-') Or  IsNamedPolygon('CS-_total_charge_current_battery') Or  IsNamedPolygon('5V')] p3: connectstyle=Direct reliefconductorwidth=0.254 reliefentries=4 polygonreliefangle="90 Angle" airgapwidth=0.254
PolygonConnect PolygonConnect_29 [All vs IsNamedPolygon('CS-_total_charge_current_battery') Or  IsNamedPolygon('CS-_total_discharge_current_bus') Or  IsNamedPolygon('5V') Or  IsNamedPolygon('48Vout1') Or  IsNamedPolygon('VBAT-') Or  IsNamedPolygon('5V') Or  IsNamedPolygon('VBAT-') Or  IsNamedPolygon('48Vout2') Or  IsNamedPolygon('VBAT-') Or  IsNamedPolygon('48Vout2') Or  IsNamedPolygon('CS-_total_charge_current_battery') Or  IsNamedPolygon('VBAT-') Or  IsNamedPolygon('48Vout1') Or  IsNamedPolygon('48Vout1') Or  IsNamedPolygon('48Vout1') Or  IsNamedPolygon('VBAT-') Or  IsNamedPolygon('48VOUT1') Or  IsNamedPolygon('5V') Or  IsNamedPolygon('CS-_total_discharge_current_bus') Or  IsNamedPolygon('5V') Or  IsNamedPolygon('VBAT-') Or  IsNamedPolygon('VBAT-') Or  IsNamedPolygon('5V') Or  IsNamedPolygon('VBAT-') Or  IsNamedPolygon('VBAT-') Or  IsNamedPolygon('VBAT-') Or  IsNamedPolygon('CS-') Or  IsNamedPolygon('5V') Or  IsNamedPolygon('VBAT-') Or  IsNamedPolygon('5V') Or  IsNamedPolygon('VBAT-') Or  IsNamedPolygon('48Vout1') Or  IsNamedPolygon('CS+_total_charge_current_battery') Or  IsNamedPolygon('VBAT-') Or  IsNamedPolygon('VBAT-') Or  IsNamedPolygon('CS-_total_charge_current_battery') Or  IsNamedPolygon('5V') Or  IsNamedPolygon('VBAT-') Or  IsNamedPolygon('48Vout1') Or  IsNamedPolygon('CS-_total_charge_current_battery') Or  IsNamedPolygon('VBAT-') Or  IsNamedPolygon('CS-') Or  IsNamedPolygon('5V') Or  IsNamedPolygon('48Vout2') Or  IsNamedPolygon('CS-_total_charge_current_battery') Or  IsNamedPolygon('VBAT-') Or  IsNamedPolygon('48Vout2') Or  IsNamedPolygon('VBAT-') Or  IsNamedPolygon('48Vout2') Or  IsNamedPolygon('CS-') Or  IsNamedPolygon('VBAT-') Or  IsNamedPolygon('VBAT-') Or  IsNamedPolygon('48V2') Or  IsNamedPolygon('CS+_total_charge_current_battery') Or  IsNamedPolygon('VBAT-') Or  IsNamedPolygon('VBAT-') Or  IsNamedPolygon('VBAT-') Or  IsNamedPolygon('CS-_total_charge_current_battery') Or  IsNamedPolygon('CS-_total_discharge_current_bus') Or  IsNamedPolygon('48Vout2') Or  IsNamedPolygon('CS-_total_discharge_current_bus') Or  IsNamedPolygon('CS-_total_discharge_current_bus') Or  IsNamedPolygon('VBAT-') Or  IsNamedPolygon('48Vout1') Or  IsNamedPolygon('CS-_total_charge_current_battery') Or  IsNamedPolygon('VBAT-') Or  IsNamedPolygon('CS-_total_charge_current_battery') Or  IsNamedPolygon('CS-_total_discharge_current_bus') Or  IsNamedPolygon('VBAT-') Or  IsNamedPolygon('VBAT-') Or  IsNamedPolygon('CS-_total_charge_current_battery') Or  IsNamedPolygon('48Vout2') Or  IsNamedPolygon('CS-_total_discharge_current_bus') Or  IsNamedPolygon('VBAT-')] p4: connectstyle=Direct reliefconductorwidth=0.254 reliefentries=4 polygonreliefangle="90 Angle" airgapwidth=0.254
PolygonConnect PolygonConnect_28 [All vs IsNamedPolygon('48VOUT1') Or  IsNamedPolygon('VBAT-') Or  IsNamedPolygon('VBAT-') Or  IsNamedPolygon('VBAT-') Or  IsNamedPolygon('VBAT-') Or  IsNamedPolygon('5V') Or  IsNamedPolygon('VBAT-') Or  IsNamedPolygon('VBAT-') Or  IsNamedPolygon('VBAT-') Or  IsNamedPolygon('48Vout1') Or  IsNamedPolygon('CS-_total_discharge_current_bus') Or  IsNamedPolygon('VBAT-') Or  IsNamedPolygon('VBAT-') Or  IsNamedPolygon('CS-') Or  IsNamedPolygon('VBAT-') Or  IsNamedPolygon('CS-_total_discharge_current_bus') Or  IsNamedPolygon('CS-_total_charge_current_battery') Or  IsNamedPolygon('48Vout2') Or  IsNamedPolygon('CS-_total_charge_current_battery') Or  IsNamedPolygon('VBAT-') Or  IsNamedPolygon('CS+_total_charge_current_battery') Or  IsNamedPolygon('48Vout1') Or  IsNamedPolygon('VBAT-') Or  IsNamedPolygon('CS-_total_charge_current_battery') Or  IsNamedPolygon('5V') Or  IsNamedPolygon('48Vout2') Or  IsNamedPolygon('CS-_total_discharge_current_bus') Or  IsNamedPolygon('5V') Or  IsNamedPolygon('VBAT-') Or  IsNamedPolygon('CS-_total_charge_current_battery') Or  IsNamedPolygon('VBAT-') Or  IsNamedPolygon('VBAT-') Or  IsNamedPolygon('48Vout2') Or  IsNamedPolygon('5V') Or  IsNamedPolygon('VBAT-') Or  IsNamedPolygon('5V') Or  IsNamedPolygon('CS-_total_discharge_current_bus') Or  IsNamedPolygon('VBAT-') Or  IsNamedPolygon('CS+_total_charge_current_battery') Or  IsNamedPolygon('VBAT-') Or  IsNamedPolygon('48Vout1') Or  IsNamedPolygon('VBAT-') Or  IsNamedPolygon('CS-_total_discharge_current_bus') Or  IsNamedPolygon('CS-_total_discharge_current_bus') Or  IsNamedPolygon('CS-_total_charge_current_battery') Or  IsNamedPolygon('VBAT-') Or  IsNamedPolygon('VBAT-') Or  IsNamedPolygon('VBAT-') Or  IsNamedPolygon('CS-_total_charge_current_battery') Or  IsNamedPolygon('48Vout2') Or  IsNamedPolygon('VBAT-') Or  IsNamedPolygon('CS-_total_charge_current_battery') Or  IsNamedPolygon('VBAT-') Or  IsNamedPolygon('48V2') Or  IsNamedPolygon('48Vout1') Or  IsNamedPolygon('5V') Or  IsNamedPolygon('48Vout2') Or  IsNamedPolygon('CS-_total_charge_current_battery') Or  IsNamedPolygon('5V') Or  IsNamedPolygon('CS-') Or  IsNamedPolygon('VBAT-') Or  IsNamedPolygon('5V') Or  IsNamedPolygon('VBAT-') Or  IsNamedPolygon('48Vout1') Or  IsNamedPolygon('CS-_total_discharge_current_bus') Or  IsNamedPolygon('48Vout1') Or  IsNamedPolygon('CS-') Or  IsNamedPolygon('5V') Or  IsNamedPolygon('48Vout2') Or  IsNamedPolygon('CS-_total_charge_current_battery') Or  IsNamedPolygon('48Vout1') Or  IsNamedPolygon('VBAT-') Or  IsNamedPolygon('48Vout2')] p5: connectstyle=Direct reliefconductorwidth=0.254 reliefentries=4 polygonreliefangle="90 Angle" airgapwidth=0.254
PolygonConnect PolygonConnect_27 [All vs IsNamedPolygon('VBAT-') Or  IsNamedPolygon('5V') Or  IsNamedPolygon('5V') Or  IsNamedPolygon('VBAT-') Or  IsNamedPolygon('VBAT-') Or  IsNamedPolygon('VBAT-') Or  IsNamedPolygon('VBAT-') Or  IsNamedPolygon('VBAT-') Or  IsNamedPolygon('CS-_total_discharge_current_bus') Or  IsNamedPolygon('48Vout1') Or  IsNamedPolygon('VBAT-') Or  IsNamedPolygon('VBAT-') Or  IsNamedPolygon('CS-_total_discharge_current_bus') Or  IsNamedPolygon('CS-_total_charge_current_battery') Or  IsNamedPolygon('CS-_total_discharge_current_bus') Or  IsNamedPolygon('5V') Or  IsNamedPolygon('VBAT-') Or  IsNamedPolygon('VBAT-') Or  IsNamedPolygon('5V') Or  IsNamedPolygon('VBAT-') Or  IsNamedPolygon('5V') Or  IsNamedPolygon('CS+_total_charge_current_battery') Or  IsNamedPolygon('VBAT-') Or  IsNamedPolygon('48Vout2') Or  IsNamedPolygon('CS-_total_charge_current_battery') Or  IsNamedPolygon('48Vout2') Or  IsNamedPolygon('48Vout2') Or  IsNamedPolygon('CS-') Or  IsNamedPolygon('VBAT-') Or  IsNamedPolygon('CS+_total_charge_current_battery') Or  IsNamedPolygon('CS-_total_discharge_current_bus') Or  IsNamedPolygon('5V') Or  IsNamedPolygon('CS-_total_charge_current_battery') Or  IsNamedPolygon('5V') Or  IsNamedPolygon('5V') Or  IsNamedPolygon('48Vout2') Or  IsNamedPolygon('48V2') Or  IsNamedPolygon('48VOUT1') Or  IsNamedPolygon('48Vout2') Or  IsNamedPolygon('48Vout2') Or  IsNamedPolygon('48Vout2') Or  IsNamedPolygon('CS-_total_discharge_current_bus') Or  IsNamedPolygon('5V') Or  IsNamedPolygon('CS-_total_discharge_current_bus') Or  IsNamedPolygon('48Vout1') Or  IsNamedPolygon('VBAT-') Or  IsNamedPolygon('CS-_total_charge_current_battery')] p6: connectstyle=Direct reliefconductorwidth=0.254 reliefentries=4 polygonreliefangle="90 Angle" airgapwidth=0.254
PolygonConnect PolygonConnect_26 [All vs IsNamedPolygon('48Vout2') Or  IsNamedPolygon('VBAT-') Or  IsNamedPolygon('VBAT-') Or  IsNamedPolygon('VBAT-') Or  IsNamedPolygon('5V') Or  IsNamedPolygon('CS-_total_discharge_current_bus') Or  IsNamedPolygon('CS-_total_charge_current_battery') Or  IsNamedPolygon('48Vout2') Or  IsNamedPolygon('48Vout1') Or  IsNamedPolygon('CS-_total_charge_current_battery') Or  IsNamedPolygon('5V') Or  IsNamedPolygon('CS+_total_charge_current_battery') Or  IsNamedPolygon('CS-_total_discharge_current_bus') Or  IsNamedPolygon('5V') Or  IsNamedPolygon('CS-_total_discharge_current_bus') Or  IsNamedPolygon('CS-_total_discharge_current_bus') Or  IsNamedPolygon('48Vout2') Or  IsNamedPolygon('VBAT-') Or  IsNamedPolygon('CS-_total_discharge_current_bus') Or  IsNamedPolygon('5V') Or  IsNamedPolygon('VBAT-') Or  IsNamedPolygon('5V') Or  IsNamedPolygon('VBAT-') Or  IsNamedPolygon('CS-_total_discharge_current_bus') Or  IsNamedPolygon('48Vout2') Or  IsNamedPolygon('48VOUT1') Or  IsNamedPolygon('48Vout1') Or  IsNamedPolygon('48Vout2') Or  IsNamedPolygon('5V') Or  IsNamedPolygon('VBAT-') Or  IsNamedPolygon('CS-_total_charge_current_battery') Or  IsNamedPolygon('48Vout2') Or  IsNamedPolygon('CS-') Or  IsNamedPolygon('VBAT-') Or  IsNamedPolygon('VBAT-') Or  IsNamedPolygon('5V') Or  IsNamedPolygon('5V') Or  IsNamedPolygon('48V2') Or  IsNamedPolygon('CS-_total_charge_current_battery') Or  IsNamedPolygon('VBAT-') Or  IsNamedPolygon('48Vout2') Or  IsNamedPolygon('CS+_total_charge_current_battery') Or  IsNamedPolygon('5V')] p7: connectstyle=Direct reliefconductorwidth=0.254 reliefentries=4 polygonreliefangle="90 Angle" airgapwidth=0.254
PolygonConnect PolygonConnect_25 [All vs IsNamedPolygon('CS-_total_discharge_current_bus') Or  IsNamedPolygon('VBAT-') Or  IsNamedPolygon('5V') Or  IsNamedPolygon('5V') Or  IsNamedPolygon('VBAT-') Or  IsNamedPolygon('CS-_total_charge_current_battery') Or  IsNamedPolygon('VBAT-') Or  IsNamedPolygon('5V') Or  IsNamedPolygon('CS-_total_discharge_current_bus') Or  IsNamedPolygon('5V') Or  IsNamedPolygon('CS-_total_charge_current_battery') Or  IsNamedPolygon('VBAT-') Or  IsNamedPolygon('CS-_total_discharge_current_bus') Or  IsNamedPolygon('48Vout2') Or  IsNamedPolygon('CS-_total_discharge_current_bus') Or  IsNamedPolygon('VBAT-') Or  IsNamedPolygon('VBAT-') Or  IsNamedPolygon('VBAT-') Or  IsNamedPolygon('CS-_total_discharge_current_bus') Or  IsNamedPolygon('48VOUT1') Or  IsNamedPolygon('CS+_total_charge_current_battery') Or  IsNamedPolygon('5V') Or  IsNamedPolygon('5V') Or  IsNamedPolygon('VBAT-') Or  IsNamedPolygon('48Vout2') Or  IsNamedPolygon('5V') Or  IsNamedPolygon('CS-_total_discharge_current_bus') Or  IsNamedPolygon('CS-_total_charge_current_battery') Or  IsNamedPolygon('48Vout2') Or  IsNamedPolygon('CS-_total_charge_current_battery') Or  IsNamedPolygon('48Vout2') Or  IsNamedPolygon('5V') Or  IsNamedPolygon('5V') Or  IsNamedPolygon('48Vout2') Or  IsNamedPolygon('CS+_total_charge_current_battery') Or  IsNamedPolygon('48V2') Or  IsNamedPolygon('VBAT-') Or  IsNamedPolygon('48Vout2')] p8: connectstyle=Direct reliefconductorwidth=0.254 reliefentries=4 polygonreliefangle="90 Angle" airgapwidth=0.254
PolygonConnect PolygonConnect_24 [All vs IsNamedPolygon('VBAT-') Or  IsNamedPolygon('VBAT-') Or  IsNamedPolygon('VBAT-') Or  IsNamedPolygon('48VOUT1') Or  IsNamedPolygon('VBAT-') Or  IsNamedPolygon('48VOUT2') Or  IsNamedPolygon('CS-_total_charge_current_battery') Or  IsNamedPolygon('VBAT-') Or  IsNamedPolygon('CS+_total_charge_current_battery') Or  IsNamedPolygon('VBAT-') Or  IsNamedPolygon('VBAT-') Or  IsNamedPolygon('VBAT-') Or  IsNamedPolygon('CS-_total_charge_current_battery') Or  IsNamedPolygon('VBAT-') Or  IsNamedPolygon('CS-_total_charge_current_battery') Or  IsNamedPolygon('48VOUT1') Or  IsNamedPolygon('AutoNaming') Or  IsNamedPolygon('VBAT-') Or  IsNamedPolygon('CS-_total_charge_current_battery') Or  IsNamedPolygon('48VOUT1') Or  IsNamedPolygon('VBAT-') Or  IsNamedPolygon('CS-_total_charge_current_battery') Or  IsNamedPolygon('48VOUT2') Or  IsNamedPolygon('48VOUT1') Or  IsNamedPolygon('12V') Or  IsNamedPolygon('VBAT-') Or  IsNamedPolygon('VBAT-') Or  IsNamedPolygon('CS+_total_charge_current_battery') Or  IsNamedPolygon('5V') Or  IsNamedPolygon('5V') Or  IsNamedPolygon('5V') Or  IsNamedPolygon('CS-_total_charge_current_battery') Or  IsNamedPolygon('CS-_total_charge_current_battery') Or  IsNamedPolygon('VBAT-') Or  IsNamedPolygon('VBAT-') Or  IsNamedPolygon('VBAT-') Or  IsNamedPolygon('5V') Or  IsNamedPolygon('VBAT-') Or  IsNamedPolygon('VBAT-') Or  IsNamedPolygon('48VOUT2') Or  IsNamedPolygon('VBAT-') Or  IsNamedPolygon('VBAT-') Or  IsNamedPolygon('VBAT-') Or  IsNamedPolygon('48VOUT1') Or  IsNamedPolygon('VBAT-') Or  IsNamedPolygon('CS+_total_charge_current_battery') Or  IsNamedPolygon('5V') Or  IsNamedPolygon('5V') Or  IsNamedPolygon('48Vout2') Or  IsNamedPolygon('CS-_total_charge_current_battery') Or  IsNamedPolygon('3V3') Or  IsNamedPolygon('CS-_total_discharge_current_bus') Or  IsNamedPolygon('CS-_total_discharge_current_bus') Or  IsNamedPolygon('CS-_total_discharge_current_bus') Or  IsNamedPolygon('CS-_total_discharge_current_bus') Or  IsNamedPolygon('CS-_total_discharge_current_bus') Or  IsNamedPolygon('48Vout2') Or  IsNamedPolygon('48Vout2') Or  IsNamedPolygon('5V') Or  IsNamedPolygon('12V') Or  IsNamedPolygon('48Vout2') Or  IsNamedPolygon('48Vout2') Or  IsNamedPolygon('48Vout2') Or  IsNamedPolygon('CS-_total_discharge_current_bus') Or  IsNamedPolygon('5V') Or  IsNamedPolygon('5V') Or  IsNamedPolygon('5V')] p9: connectstyle=Direct reliefconductorwidth=0.254 reliefentries=4 polygonreliefangle="90 Angle" airgapwidth=0.254
PolygonConnect PolygonConnect_23 [All vs IsNamedPolygon('5V') Or  IsNamedPolygon('12V') Or  IsNamedPolygon('CS+_total_charge_current_battery') Or  IsNamedPolygon('CS-_total_charge_current_battery') Or  IsNamedPolygon('5V') Or  IsNamedPolygon('VBAT-') Or  IsNamedPolygon('48VOUT1') Or  IsNamedPolygon('48VOUT1') Or  IsNamedPolygon('5V') Or  IsNamedPolygon('VBAT-') Or  IsNamedPolygon('VBAT-') Or  IsNamedPolygon('48Vout2') Or  IsNamedPolygon('VBAT-') Or  IsNamedPolygon('VBAT-') Or  IsNamedPolygon('48Vout2') Or  IsNamedPolygon('5V') Or  IsNamedPolygon('5V') Or  IsNamedPolygon('VBAT-') Or  IsNamedPolygon('CS-_total_discharge_current_bus') Or  IsNamedPolygon('VBAT-') Or  IsNamedPolygon('VBAT-') Or  IsNamedPolygon('48Vout2') Or  IsNamedPolygon('VBAT-') Or  IsNamedPolygon('CS-_total_charge_current_battery') Or  IsNamedPolygon('48VOUT2') Or  IsNamedPolygon('48Vout2') Or  IsNamedPolygon('CS-_total_discharge_current_bus') Or  IsNamedPolygon('VBAT-') Or  IsNamedPolygon('48Vout2') Or  IsNamedPolygon('CS-_total_charge_current_battery') Or  IsNamedPolygon('CS-_total_charge_current_battery') Or  IsNamedPolygon('5V') Or  IsNamedPolygon('48VOUT2') Or  IsNamedPolygon('CS-_total_charge_current_battery') Or  IsNamedPolygon('5V') Or  IsNamedPolygon('CS-_total_discharge_current_bus') Or  IsNamedPolygon('CS+_total_charge_current_battery') Or  IsNamedPolygon('CS-_total_discharge_current_bus') Or  IsNamedPolygon('48Vout2') Or  IsNamedPolygon('CS-_total_discharge_current_bus') Or  IsNamedPolygon('CS-_total_charge_current_battery') Or  IsNamedPolygon('5V') Or  IsNamedPolygon('CS-_total_discharge_current_bus') Or  IsNamedPolygon('VBAT-')] p10: connectstyle=Direct reliefconductorwidth=0.254 reliefentries=4 polygonreliefangle="90 Angle" airgapwidth=0.254
PolygonConnect PolygonConnect_22 [All vs IsNamedPolygon('5V') Or  IsNamedPolygon('VBAT-') Or  IsNamedPolygon('CS-_total_discharge_current_bus') Or  IsNamedPolygon('CS-_total_discharge_current_bus') Or  IsNamedPolygon('5V') Or  IsNamedPolygon('CS-_total_discharge_current_bus') Or  IsNamedPolygon('VBAT-') Or  IsNamedPolygon('48Vout2') Or  IsNamedPolygon('48Vout2') Or  IsNamedPolygon('48Vout2') Or  IsNamedPolygon('48VOUT2') Or  IsNamedPolygon('CS-_total_discharge_current_bus') Or  IsNamedPolygon('CS-_total_charge_current_battery') Or  IsNamedPolygon('48Vout2') Or  IsNamedPolygon('CS+_total_charge_current_battery') Or  IsNamedPolygon('12V') Or  IsNamedPolygon('CS-_total_discharge_current_bus') Or  IsNamedPolygon('48Vout2') Or  IsNamedPolygon('CS-_total_charge_current_battery') Or  IsNamedPolygon('48Vout2') Or  IsNamedPolygon('CS-_total_discharge_current_bus') Or  IsNamedPolygon('VBAT-') Or  IsNamedPolygon('48VOUT2') Or  IsNamedPolygon('48VOUT1') Or  IsNamedPolygon('VBAT-')] p11: connectstyle=Direct reliefconductorwidth=0.254 reliefentries=4 polygonreliefangle="90 Angle" airgapwidth=0.254
PolygonConnect PolygonConnect_21 [All vs IsNamedPolygon('CS+_total_charge_current_battery') Or  IsNamedPolygon('CS-_total_discharge_current_bus') Or  IsNamedPolygon('48Vout2') Or  IsNamedPolygon('CS-_total_discharge_current_bus') Or  IsNamedPolygon('48Vout2') Or  IsNamedPolygon('CS-_total_discharge_current_bus') Or  IsNamedPolygon('12V') Or  IsNamedPolygon('CS-_total_discharge_current_bus') Or  IsNamedPolygon('5V') Or  IsNamedPolygon('48Vout2') Or  IsNamedPolygon('48Vout2') Or  IsNamedPolygon('CS-_total_discharge_current_bus') Or  IsNamedPolygon('CS-_total_charge_current_battery') Or  IsNamedPolygon('5V') Or  IsNamedPolygon('48Vout2') Or  IsNamedPolygon('VBAT-') Or  IsNamedPolygon('48Vout2') Or  IsNamedPolygon('CS-_total_discharge_current_bus')] p12: connectstyle=Direct reliefconductorwidth=0.254 reliefentries=4 polygonreliefangle="90 Angle" airgapwidth=0.254
PolygonConnect PolygonConnect_20 [All vs IsNamedPolygon('48Vout2') Or  IsNamedPolygon('CS+_total_charge_current_battery') Or  IsNamedPolygon('48Vout2') Or  IsNamedPolygon('5V') Or  IsNamedPolygon('12V') Or  IsNamedPolygon('48Vout2') Or  IsNamedPolygon('48Vout2') Or  IsNamedPolygon('48Vout2') Or  IsNamedPolygon('48Vout2') Or  IsNamedPolygon('CS-_total_charge_current_battery') Or  IsNamedPolygon('VBAT-') Or  IsNamedPolygon('5V')] p13: connectstyle=Direct reliefconductorwidth=0.254 reliefentries=4 polygonreliefangle="90 Angle" airgapwidth=0.254
PolygonConnect PolygonConnect_19 [All vs IsNamedPolygon('VBAT-') Or  IsNamedPolygon('VBAT-') Or  IsNamedPolygon('VBAT-') Or  IsNamedPolygon('SW2') Or  IsNamedPolygon('VBAT_DISCH_IN') Or  IsNamedPolygon('VBAT_DISCH_IN') Or  IsNamedPolygon('VBAT_DISCH_IN') Or  IsNamedPolygon('CSB_DISCH') Or  IsNamedPolygon('VBAT-') Or  IsNamedPolygon('5V') Or  IsNamedPolygon('VBAT-') Or  IsNamedPolygon('SNGD') Or  IsNamedPolygon('VBAT-') Or  IsNamedPolygon('VBAT-') Or  IsNamedPolygon('SW2') Or  IsNamedPolygon('VBAT-') Or  IsNamedPolygon('VBAT-') Or  IsNamedPolygon('CSA_DISCH') Or  IsNamedPolygon('48V_DISCH_OUT') Or  IsNamedPolygon('VBAT_DISCH_IN') Or  IsNamedPolygon('VBAT-') Or  IsNamedPolygon('VBAT-') Or  IsNamedPolygon('48V_DISCH_OUT') Or  IsNamedPolygon('VBAT-') Or  IsNamedPolygon('CSA_DISCH') Or  IsNamedPolygon('5V') Or  IsNamedPolygon('VBAT-') Or  IsNamedPolygon('VBAT-') Or  IsNamedPolygon('48V_DISCH_OUT') Or  IsNamedPolygon('48V_DISCH_OUT') Or  IsNamedPolygon('VBAT-') Or  IsNamedPolygon('12V_AUX') Or  IsNamedPolygon('48V_DISCH_OUT') Or  IsNamedPolygon('VBAT_DISCH_IN') Or  IsNamedPolygon('VBAT_DISCH_IN') Or  IsNamedPolygon('VBAT-')] p14: connectstyle=Direct reliefconductorwidth=0.254 reliefentries=4 polygonreliefangle="90 Angle" airgapwidth=0.254
PolygonConnect PolygonConnect_18 [All vs IsNamedPolygon('SW2') Or  IsNamedPolygon('VBAT_DISCH_IN') Or  IsNamedPolygon('VBAT_DISCH_IN') Or  IsNamedPolygon('VBAT_DISCH_IN') Or  IsNamedPolygon('48V_DISCH_OUT') Or  IsNamedPolygon('VBAT_DISCH_IN') Or  IsNamedPolygon('VBAT-') Or  IsNamedPolygon('VBAT-') Or  IsNamedPolygon('VBAT-') Or  IsNamedPolygon('VBAT-') Or  IsNamedPolygon('VBAT-') Or  IsNamedPolygon('VBAT_DISCH_IN') Or  IsNamedPolygon('VBAT-') Or  IsNamedPolygon('CSA_DISCH') Or  IsNamedPolygon('VBAT-') Or  IsNamedPolygon('48V_DISCH_OUT') Or  IsNamedPolygon('48V_DISCH_OUT') Or  IsNamedPolygon('5V') Or  IsNamedPolygon('VBAT-') Or  IsNamedPolygon('VBAT-') Or  IsNamedPolygon('VBAT-') Or  IsNamedPolygon('VBAT-') Or  IsNamedPolygon('12V_AUX') Or  IsNamedPolygon('CSA_DISCH') Or  IsNamedPolygon('CSB_DISCH') Or  IsNamedPolygon('VBAT-') Or  IsNamedPolygon('VBAT-') Or  IsNamedPolygon('VBAT_DISCH_IN')] p15: connectstyle=Direct reliefconductorwidth=0.254 reliefentries=4 polygonreliefangle="90 Angle" airgapwidth=0.254
PolygonConnect PolygonConnect_17 [All vs IsNamedPolygon('VBAT-') Or  IsNamedPolygon('VBAT_DISCH_IN') Or  IsNamedPolygon('VBAT-') Or  IsNamedPolygon('VBAT_DISCH_IN') Or  IsNamedPolygon('CSA_DISCH') Or  IsNamedPolygon('VBAT_DISCH_IN') Or  IsNamedPolygon('VBAT_DISCH_IN') Or  IsNamedPolygon('VBAT-') Or  IsNamedPolygon('VBAT-') Or  IsNamedPolygon('48V_DISCH_OUT') Or  IsNamedPolygon('CSA_DISCH') Or  IsNamedPolygon('VBAT-') Or  IsNamedPolygon('VBAT_DISCH_IN') Or  IsNamedPolygon('VBAT-') Or  IsNamedPolygon('5V') Or  IsNamedPolygon('48V_DISCH_OUT') Or  IsNamedPolygon('VBAT-') Or  IsNamedPolygon('CSB_DISCH') Or  IsNamedPolygon('SW2') Or  IsNamedPolygon('VBAT-') Or  IsNamedPolygon('48V_DISCH_OUT') Or  IsNamedPolygon('VBAT-') Or  IsNamedPolygon('VBAT_DISCH_IN')] p16: connectstyle=Direct reliefconductorwidth=0.254 reliefentries=4 polygonreliefangle="90 Angle" airgapwidth=0.254
PolygonConnect PolygonConnect_16 [All vs IsNamedPolygon('VBAT-') Or  IsNamedPolygon('VBAT-') Or  IsNamedPolygon('CSA_DISCH') Or  IsNamedPolygon('48V_DISCH_OUT') Or  IsNamedPolygon('VBAT_DISCH_IN') Or  IsNamedPolygon('VBAT-') Or  IsNamedPolygon('VBAT-') Or  IsNamedPolygon('VBAT-') Or  IsNamedPolygon('VBAT-') Or  IsNamedPolygon('VBAT_DISCH_IN') Or  IsNamedPolygon('VBAT_DISCH_IN') Or  IsNamedPolygon('CSB_DISCH') Or  IsNamedPolygon('VBAT-') Or  IsNamedPolygon('VBAT_DISCH_IN') Or  IsNamedPolygon('VBAT_DISCH_IN') Or  IsNamedPolygon('VBAT-') Or  IsNamedPolygon('VBAT_DISCH_IN') Or  IsNamedPolygon('SW2') Or  IsNamedPolygon('CSA_DISCH') Or  IsNamedPolygon('VBAT-')] p17: connectstyle=Direct reliefconductorwidth=0.254 reliefentries=4 polygonreliefangle="90 Angle" airgapwidth=0.254
PolygonConnect PolygonConnect_15 [All vs IsNamedPolygon('CSA_DISCH') Or  IsNamedPolygon('VBAT-') Or  IsNamedPolygon('VBAT-') Or  IsNamedPolygon('48V_DISCH_OUT') Or  IsNamedPolygon('VBAT_DISCH_IN') Or  IsNamedPolygon('SW2') Or  IsNamedPolygon('VBAT_DISCH_IN') Or  IsNamedPolygon('VBAT-') Or  IsNamedPolygon('VBAT_DISCH_IN') Or  IsNamedPolygon('CSB_DISCH') Or  IsNamedPolygon('VBAT_DISCH_IN') Or  IsNamedPolygon('CSA_DISCH') Or  IsNamedPolygon('VBAT_DISCH_IN')] p18: connectstyle=Direct reliefconductorwidth=0.254 reliefentries=4 polygonreliefangle="90 Angle" airgapwidth=0.254
PolygonConnect PolygonConnect_14 [All vs IsNamedPolygon('SW2') Or  IsNamedPolygon('48V_DISCH_OUT') Or  IsNamedPolygon('VBAT-') Or  IsNamedPolygon('VBAT-') Or  IsNamedPolygon('CSA_DISCH') Or  IsNamedPolygon('CSB_DISCH')] p19: connectstyle=Direct reliefconductorwidth=0.254 reliefentries=4 polygonreliefangle="90 Angle" airgapwidth=0.254
PolygonConnect PolygonConnect_13 [All vs IsNamedPolygon('VBAT-') Or  IsNamedPolygon('48V_DISCH_OUT') Or  IsNamedPolygon('VBAT-') Or  IsNamedPolygon('CSB_DISCH') Or  IsNamedPolygon('CSA_DISCH')] p20: connectstyle=Direct reliefconductorwidth=0.254 reliefentries=4 polygonreliefangle="90 Angle" airgapwidth=0.254
PolygonConnect PolygonConnect_12 [All vs IsNamedPolygon('48V_DISCH_OUT') Or  IsNamedPolygon('VBAT-') Or  IsNamedPolygon('VBAT-')] p21: connectstyle=Direct reliefconductorwidth=0.254 reliefentries=4 polygonreliefangle="90 Angle" airgapwidth=0.254
PolygonConnect PolygonConnect_11 [All vs IsNamedPolygon('GND') Or  IsNamedPolygon('D101_2') Or  IsNamedPolygon('V+') Or  IsNamedPolygon('GND') Or  IsNamedPolygon('C128_1') Or  IsNamedPolygon('J2_2') Or  IsNamedPolygon('CS') Or  IsNamedPolygon('V+') Or  IsNamedPolygon('GND') Or  IsNamedPolygon('J2_2') Or  IsNamedPolygon('PGND') Or  IsNamedPolygon('12V') Or  IsNamedPolygon('PGND') Or  IsNamedPolygon('PGND') Or  IsNamedPolygon('V+') Or  IsNamedPolygon('V+') Or  IsNamedPolygon('D101_2') Or  IsNamedPolygon('CS') Or  IsNamedPolygon('GND')] p22: connectstyle=Direct reliefconductorwidth=0.254 reliefentries=4 polygonreliefangle="90 Angle" airgapwidth=0.254
PolygonConnect PolygonConnect_10 [All vs IsNamedPolygon('GND') Or  IsNamedPolygon('C128_1') Or  IsNamedPolygon('GND') Or  IsNamedPolygon('J2_2') Or  IsNamedPolygon('GND') Or  IsNamedPolygon('D101_2') Or  IsNamedPolygon('J2_2') Or  IsNamedPolygon('V+') Or  IsNamedPolygon('PGND') Or  IsNamedPolygon('CS') Or  IsNamedPolygon('V+')] p23: connectstyle=Direct reliefconductorwidth=0.254 reliefentries=4 polygonreliefangle="90 Angle" airgapwidth=0.254
PolygonConnect PolygonConnect_9 [All vs IsNamedPolygon('J2_2') Or  IsNamedPolygon('GND') Or  IsNamedPolygon('8V5') Or  IsNamedPolygon('V+') Or  IsNamedPolygon('R117_1') Or  IsNamedPolygon('PGND') Or  IsNamedPolygon('PGND') Or  IsNamedPolygon('Drv') Or  IsNamedPolygon('V+') Or  IsNamedPolygon('V+') Or  IsNamedPolygon('C128_1') Or  IsNamedPolygon('GND') Or  IsNamedPolygon('GND') Or  IsNamedPolygon('J2_2') Or  IsNamedPolygon('PGND')] p24: connectstyle=Direct reliefconductorwidth=0.254 reliefentries=4 polygonreliefangle="90 Angle" airgapwidth=0.254
PolygonConnect PolygonConnect_8 [All vs IsNamedPolygon('8V5') Or  IsNamedPolygon('J2_2') Or  IsNamedPolygon('PGND') Or  IsNamedPolygon('GND') Or  IsNamedPolygon('GND') Or  IsNamedPolygon('V+') Or  IsNamedPolygon('J2_2') Or  IsNamedPolygon('V+') Or  IsNamedPolygon('C128_1') Or  IsNamedPolygon('V+') Or  IsNamedPolygon('PGND') Or  IsNamedPolygon('J2_2') Or  IsNamedPolygon('J2_2') Or  IsNamedPolygon('R117_1')] p25: connectstyle=Direct reliefconductorwidth=0.254 reliefentries=4 polygonreliefangle="90 Angle" airgapwidth=0.254
PolygonConnect PolygonConnect_7 [All vs IsNamedPolygon('J2_2') Or  IsNamedPolygon('J2_2') Or  IsNamedPolygon('J2_2') Or  IsNamedPolygon('C128_1') Or  IsNamedPolygon('J2_2')] p26: connectstyle=Direct reliefconductorwidth=0.254 reliefentries=4 polygonreliefangle="90 Angle" airgapwidth=0.254
PolygonConnect PolygonConnect_6 [All vs IsNamedPolygon('J2_2')] p27: connectstyle=Direct reliefconductorwidth=0.254 reliefentries=4 polygonreliefangle="90 Angle" airgapwidth=0.254
PolygonConnect PolygonConnect_5 [All vs IsNamedPolygon('GND') Or  IsNamedPolygon('Vout') Or  IsNamedPolygon('Bottom Layer-SW') Or  IsNamedPolygon('GND') Or  IsNamedPolygon('C1_1') Or  IsNamedPolygon('Q1_3') Or  IsNamedPolygon('J2_2') Or  IsNamedPolygon('GND') Or  IsNamedPolygon('J2_2') Or  IsNamedPolygon('GND') Or  IsNamedPolygon('Vout') Or  IsNamedPolygon('Top Layer-SW') Or  IsNamedPolygon('Q1_3') Or  IsNamedPolygon('GND') Or  IsNamedPolygon('J2_2') Or  IsNamedPolygon('J2_2') Or  IsNamedPolygon('GND') Or  IsNamedPolygon('GND') Or  IsNamedPolygon('GND') Or  IsNamedPolygon('GND') Or  IsNamedPolygon('GND')] p28: connectstyle=Direct reliefconductorwidth=0.254 reliefentries=4 polygonreliefangle="90 Angle" airgapwidth=0.254
PolygonConnect PolygonConnect_4 [All vs IsNamedPolygon('GND') Or  IsNamedPolygon('Bottom Layer-SW') Or  IsNamedPolygon('C1_1') Or  IsNamedPolygon('Top Layer-SW') Or  IsNamedPolygon('GND') Or  IsNamedPolygon('GND') Or  IsNamedPolygon('GND') Or  IsNamedPolygon('Q1_3') Or  IsNamedPolygon('Vout') Or  IsNamedPolygon('Q1_3') Or  IsNamedPolygon('Vout')] p29: connectstyle=Direct reliefconductorwidth=0.254 reliefentries=4 polygonreliefangle="90 Angle" airgapwidth=0.254
PolygonConnect PolygonConnect_3 [All vs IsNamedPolygon('Q1_3') Or  IsNamedPolygon('Q1_3') Or  IsNamedPolygon('Top Layer-SW') Or  IsNamedPolygon('C1_1') Or  IsNamedPolygon('Bottom Layer-SW')] p30: connectstyle=Direct reliefconductorwidth=0.254 reliefentries=4 polygonreliefangle="90 Angle" airgapwidth=0.254
PolygonConnect PolygonConnect_2 [All vs IsNamedPolygon('Top Layer-SW') Or  IsNamedPolygon('Bottom Layer-SW')] p31: connectstyle=Direct reliefconductorwidth=0.254 reliefentries=4 polygonreliefangle="90 Angle" airgapwidth=0.254
PolygonConnect PolygonConnect_1 [All vs IsNamedPolygon('Bottom Layer-SW') Or  IsNamedPolygon('Top Layer-SW')] p32: thpad.connectstyle=Direct thpad.reliefconductorwidth=0.254 thpad.reliefentries=4 thpad.polygonreliefangle="90 Angle" thpad.airgapwidth=0.254 smdpad.connectstyle=Direct smdpad.reliefconductorwidth=0.254 smdpad.reliefentries=4 smdpad.polygonreliefangle="90 Angle" smdpad.airgapwidth=0.254 via.connectstyle=Relief via.reliefconductorwidth=0.254 via.reliefentries=4 via.polygonreliefangle="90 Angle" via.airgapwidth=0.254
PolygonConnect [All] p33: connectstyle=Direct reliefconductorwidth=0.254 reliefentries=4 polygonreliefangle="90 Angle" airgapwidth=0.254
RoutingVias ThermalPadVias [IsVia and InAnyComponent] p1: holewidth=0.2 width=0.5 viastyle="Through Hole" minholewidth=0.2 minwidth=0.5 maxholewidth=0.635 maxwidth=0.914
RoutingVias [All] p2: holewidth=0.254 width=0.508 viastyle="Through Hole" minholewidth=0.2 minwidth=0.508 maxholewidth=1.016 maxwidth=1.651
SilkToBoardRegionClearance [Not ((IsComment or IsDesignator) And (Hide <> 'False')) and not InRegion(1000,500,4000,800)] p1:
SilkToSilkClearance SilkToSilkClearance_Pb-FreeLogo [(HasFootprint('Pb-Free_Overlay_Medium') OR HasFootprint('Pb-Free_Overlay_Small')) vs (HasFootprint('Pb-Free_Overlay_Medium') OR HasFootprint('Pb-Free_Overlay_Small'))] p1: silktosilkclearance=0
SilkToSilkClearance [All] p2: silktosilkclearance=0.102
SilkToSolderMaskClearance SilkToComponentPadClearance [(IsPad or IsFill or IsRegion) and InAnycomponent] p1: minsilkscreentomaskgap=0.127 clearancetoexposedcopper=TRUE
SilkToSolderMaskClearance "Silk to Solder Mask Opening" [All] p2: minsilkscreentomaskgap=0.102 clearancetoexposedcopper=FALSE
SolderMaskExpansion [All] p1: expansion=0.05 istentingtop=FALSE
SupplyNets "Schematic Supply Nets_1" [InNet('SGND')] p1: voltage=0.000
Width [All] p1: maxlimit=5 minlimit=0.2 preferedwidth=0.3 checkconnectedcopper=TRUE
14 further rules are at their usual default settings.

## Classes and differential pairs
component class PMP41155_Main_Control: C222 C223 C224 C225 C226 C227 C228 C229 C230 C231 C232 C233 C234 D201 J202 J203 Q205 Q206 Q207 Q208 Q209 Q210 Q211 R235 R236 R237 R238 R239 R240 R241 R242 R243 R244 R245 R246 R247 R248 R249 R250 R251 R252 R253 R254 R255 R256 R257 R258 R259 R260 R261 R262 R263 R264 R265 R266 R267 R268 R269 U206 U207
component class "PMP41155_Main_Control 1": C406 C407 C408 C409 C410 C411 C412 C413 C414 C415 C416 C417 C418 C419 C420 C421 C422 C423 C424 C425 C426 C430 C431 J400 R408 R409 R410 R411 R412 R413 R414 R415 R416 R417 R418 R419 R420 R421 R422 R423 R424 R425 R426 R427 R428 R429 R430 R431 R432 R433 R434 R435 R436 R437 R438 R439 R440 R441 R442 R443 R444 R445 R446 R447 R448 R449 R450 R451 R452 R453 R454 R455 R456 R457 R458 R459 R460 R470 R471 R472 R473 U401 U402
component class PMP41155_Main_Connection: C1 C2 C3 C4 C5 C400 C401 C402 C403 C404 C405 D400 Q400 Q401 Q402 Q403 R2 R400 R401 R402 R403 R404 R405 R406 R407 RT400 U400
component class "PMP41155_Main_Control 2": 200 C200 C201 C202 C203 C204 C205 C206 C207 C208 C209 C210 C211 C212 C213 C214 C215 C216 C217 C218 C219 C220 C221 C235 C236 CC203 D200 J200 J201 Q200 Q201 Q202 Q203 Q204 R200 R201 R202 R203 R204 R205 R206 R207 R208 R209 R210 R211 R212 R213 R214 R215 R216 R217 R218 R219 R220 R221 R222 R223 R224 R225 R226 R227 R228 R229 R230 R231 R232 R233 R234 R270 R271 SGND200 U200 U201 U202 U204
component class PMP41155_Main: C300 C301 C302 C306 C307 F300 F301 F302 F303 F304 F305 R300 R301 R302 R303 R304 R305 R306 R307

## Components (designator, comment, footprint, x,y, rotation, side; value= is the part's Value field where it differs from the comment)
C200 "C0402C103K4RACTU" 0402 71.109,15.475 r180 bottom value=0.01uF
C201 "06035A680JAT2A" 0603 45.131,38.25 r270 top value=68pF
C202 "0603YC104K4T4A" 0603 70.634,22.905 r90 bottom value=0.1uF
C203 "885012107013" WCAP-CSGP_0805_L2W1.25H1.25 65.205,19.475 r0 bottom
C204 "GRM1555C1H470FA01D" 0402 46.782,41.043 r0 top value=47pF
C205 "GRM1555C1H470FA01D" 0402 47.278,35.71 r0 top value=47pF
C206 "C1608X7R1C105K080AC" 0603 51.221,38.377 r270 top value=1uF
C207 "GRM155R70J104KA01D" 0402 49.83,38.123 r270 top value=0.1uF
C208 "C0603C100F5GAC7867" 0603 47.173,42.468 r180 top value=10pF
C209 "885012205061" WCAP-CSGP_0402_L1W0.5H0.5 68.99,14.53 r0 bottom
C210 "GRM155R70J104KA01D" 0402 66.679,17.779 r180 bottom value=0.1uF
C211 "06035A680JAT2A" 0603 52.288,41.903 r180 bottom value=68pF
C212 "GRM1555C1H470FA01D" 0402 55.805,41.904 r0 bottom value=47pF
C213 "GRM1555C1H470FA01D" 0402 49.188,44.453 r90 bottom value=47pF
C214 "C1608X7R1C105K080AC" 0603 56.205,44.928 r0 bottom value=1uF
C215 "GRM155R70J104KA01D" 0402 56.435,43.528 r0 bottom value=0.1uF
C216 "C0603C100F5GAC7867" 0603 58.675,45.653 r270 bottom value=10pF
C217 "GCM188R71C105KA64J" 0603 49.06,24.314 r0 top value=1uF
C218 "GRM155R70J104KA01D" 0402 48.77,22.804 r0 top value=0.1uF
C219 "885012205061" WCAP-CSGP_0402_L1W0.5H0.5 65.254,22.905 r180 bottom
C220 "C0603C100F5GAC7867" 0603 58.66,28.894 r90 top value=10pF
C221 "06035C100KAT2A" FP-06035C100KAT2A_0603-MFG 53.26,31.694 r180 top value=10pF
C222 "C0603C474K4RAC7867" FP-C0603C474K4RAC7867_0603-MFG 37.117,136.877 r180 bottom value=470nF
C223 "0603ZC100KAT2A" 0603 12.55,78.709 r0 bottom value=10pF
C224 "CMP-0006623-2" 0402 37.07,143.707 r0 bottom value=0.1uF
C225 "0603ZC100KAT2A" 0603 32.85,78.71 r0 bottom value=10pF
C226 "0603ZC100KAT2A" 0603 52.71,78.58 r0 bottom value=10pF
C227 "0603ZC100KAT2A" 0603 33.054,120.703 r0 bottom value=10pF
C228 "0603ZC100KAT2A" 0603 12.575,121.366 r0 bottom value=10pF
C229 "0603ZC100KAT2A" 0603 53.145,120.703 r0 bottom value=10pF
